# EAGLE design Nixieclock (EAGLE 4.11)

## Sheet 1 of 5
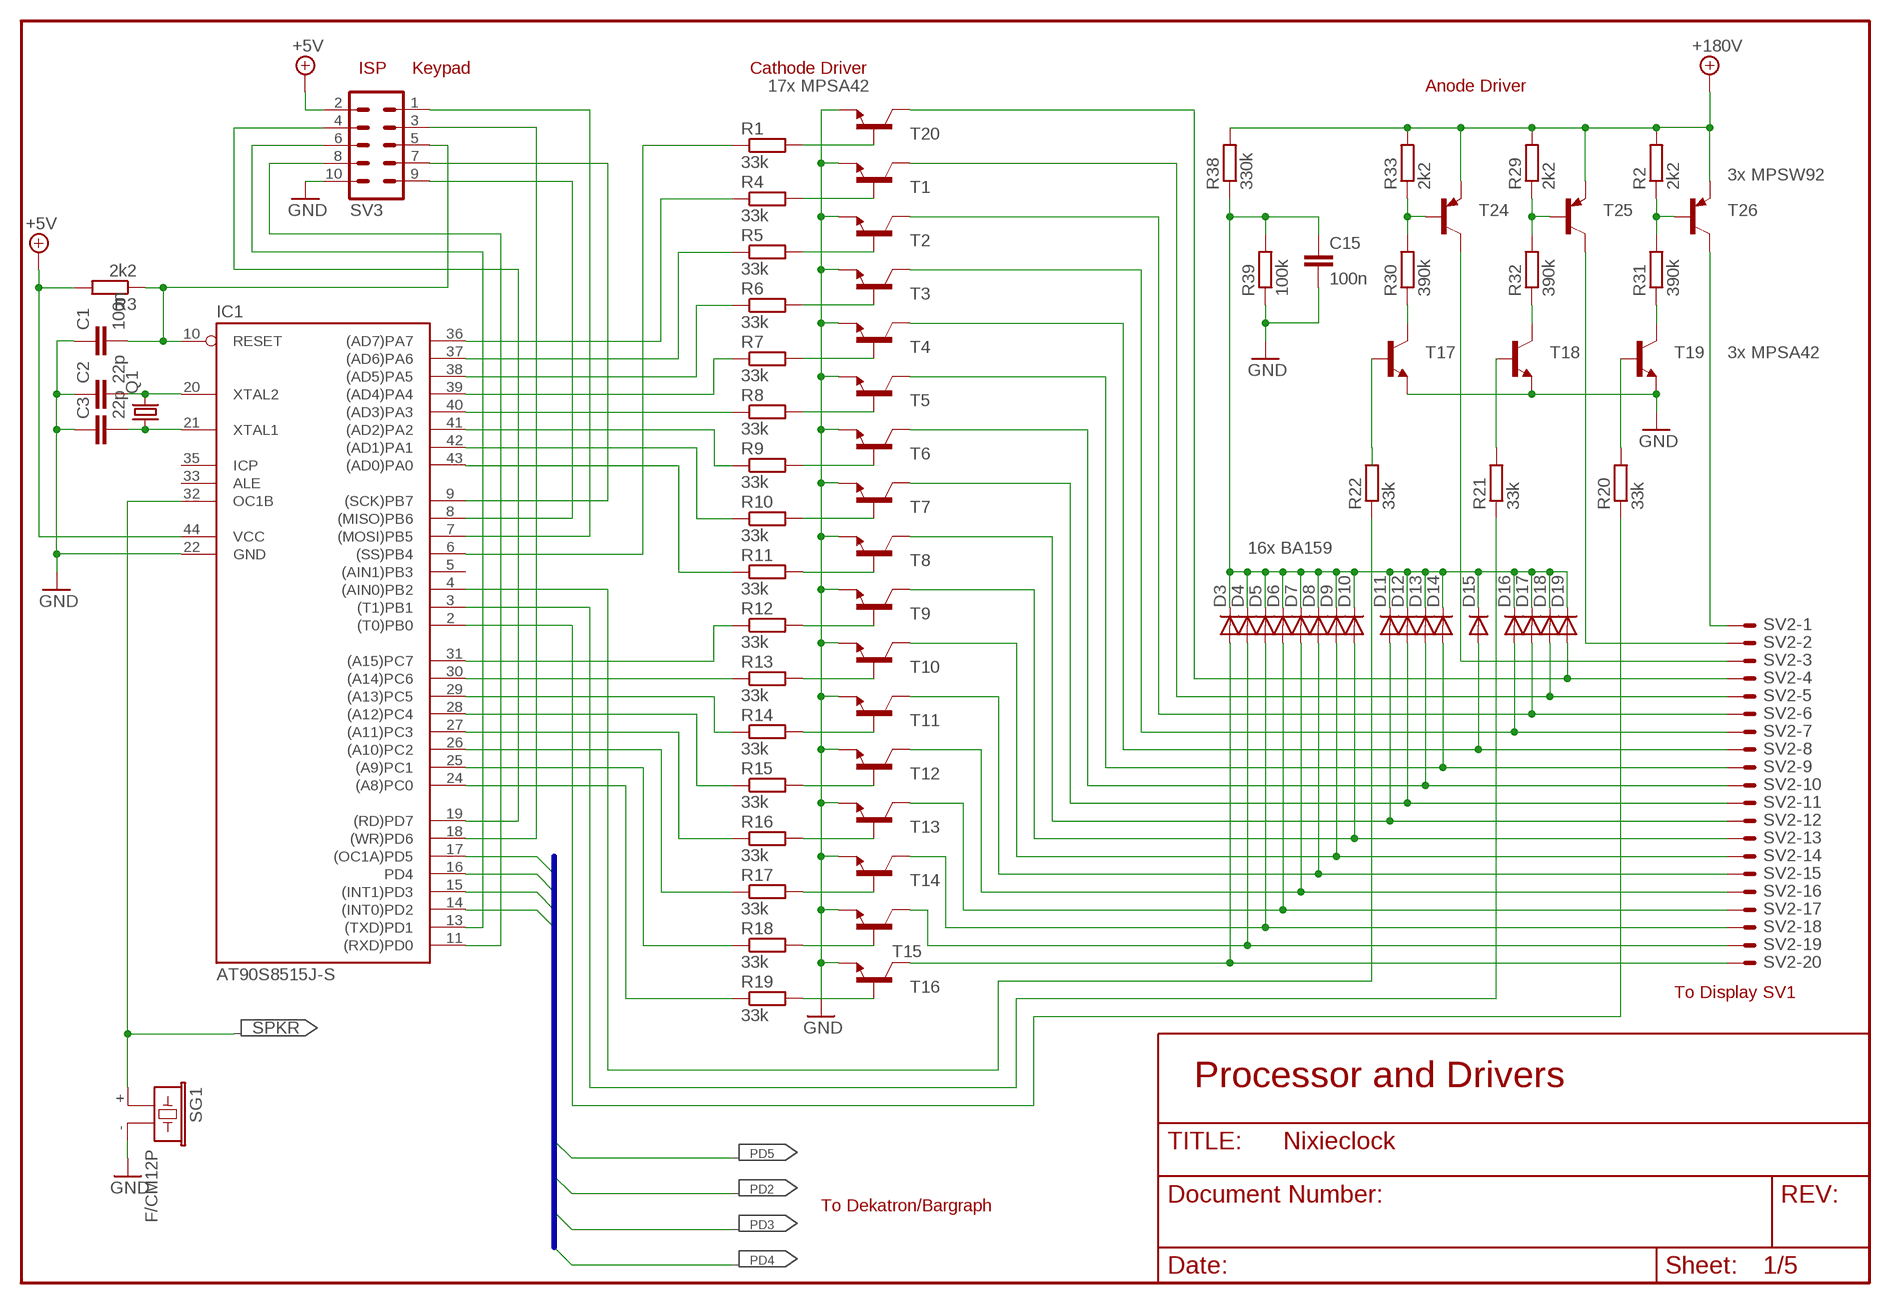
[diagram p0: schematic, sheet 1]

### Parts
C1  100n  C-EU025-024X044  [C025-024X044]
C2  22p  C-EU025-024X044  [C025-024X044]
C3  22p  C-EU025-024X044  [C025-024X044]
C15  100n  C-EU050-024X044  [C050-024X044]
D3  DIODE-D-7.5  [D-7.5]
D4  DIODE-D-7.5  [D-7.5]
D5  DIODE-D-7.5  [D-7.5]
D6  DIODE-D-7.5  [D-7.5]
D7  DIODE-D-7.5  [D-7.5]
D8  DIODE-D-7.5  [D-7.5]
D9  DIODE-D-7.5  [D-7.5]
D10  DIODE-D-7.5  [D-7.5]
D11  DIODE-D-7.5  [D-7.5]
D12  DIODE-D-7.5  [D-7.5]
D13  DIODE-D-7.5  [D-7.5]
D14  DIODE-D-7.5  [D-7.5]
D15  DIODE-D-7.5  [D-7.5]
D16  DIODE-D-7.5  [D-7.5]
D17  DIODE-D-7.5  [D-7.5]
D18  DIODE-D-7.5  [D-7.5]
D19  DIODE-D-7.5  [D-7.5]
IC1  AT90S8515J-S  [S44]
Q1  CRYTALHC49S  [HC49/S]
R1  33k  R-EU_0204/7  [0204/7]
R2  2k2  R-EU_0204/7  [0204/7]
R3  2k2  R-EU_0204/7  [0204/7]
R4  33k  R-EU_0204/7  [0204/7]
R5  33k  R-EU_0204/7  [0204/7]
R6  33k  R-EU_0204/7  [0204/7]
R7  33k  R-EU_0204/7  [0204/7]
R8  33k  R-EU_0204/7  [0204/7]
R9  33k  R-EU_0204/7  [0204/7]
R10  33k  R-EU_0204/7  [0204/7]
R11  33k  R-EU_0204/7  [0204/7]
R12  33k  R-EU_0204/7  [0204/7]
R13  33k  R-EU_0204/7  [0204/7]
R14  33k  R-EU_0204/7  [0204/7]
R15  33k  R-EU_0204/7  [0204/7]
R16  33k  R-EU_0204/7  [0204/7]
R17  33k  R-EU_0204/7  [0204/7]
R18  33k  R-EU_0204/7  [0204/7]
R19  33k  R-EU_0204/7  [0204/7]
R20  33k  R-EU_0204/7  [0204/7]
R21  33k  R-EU_0204/7  [0204/7]
R22  33k  R-EU_0204/7  [0204/7]
R29  2k2  R-EU_0204/7  [0204/7]
R30  390k  R-EU_0204/7  [0204/7]
R31  390k  R-EU_0204/7  [0204/7]
R32  390k  R-EU_0204/7  [0204/7]
R33  2k2  R-EU_0204/7  [0204/7]
R38  330k  R-EU_0207/7  [0207/7]
R39  100k  R-EU_0207/7  [0207/7]
SG1  F/CM12P  [F/CM12P]
SV2  ML20E  [ML20]
SV3  ML10  [ML10]
T1  MPSA42-NPN-TO92-CBE  [TO92-CBE]
T2  MPSA42-NPN-TO92-CBE  [TO92-CBE]
T3  MPSA42-NPN-TO92-CBE  [TO92-CBE]
T4  MPSA42-NPN-TO92-CBE  [TO92-CBE]
T5  MPSA42-NPN-TO92-CBE  [TO92-CBE]
T6  MPSA42-NPN-TO92-CBE  [TO92-CBE]
T7  MPSA42-NPN-TO92-CBE  [TO92-CBE]
T8  MPSA42-NPN-TO92-CBE  [TO92-CBE]
T9  MPSA42-NPN-TO92-CBE  [TO92-CBE]
T10  MPSA42-NPN-TO92-CBE  [TO92-CBE]
T11  MPSA42-NPN-TO92-CBE  [TO92-CBE]
T12  MPSA42-NPN-TO92-CBE  [TO92-CBE]
T13  MPSA42-NPN-TO92-CBE  [TO92-CBE]
T14  MPSA42-NPN-TO92-CBE  [TO92-CBE]
T15  MPSA42-NPN-TO92-CBE  [TO92-CBE]
T16  MPSA42-NPN-TO92-CBE  [TO92-CBE]
T17  MPSA42-NPN-TO92-CBE  [TO92-CBE]
T18  MPSA42-NPN-TO92-CBE  [TO92-CBE]
T19  MPSA42-NPN-TO92-CBE  [TO92-CBE]
T20  MPSA42-NPN-TO92-CBE  [TO92-CBE]
T24  MPSW92-PNP-TO92-CBE  [TO92-CBE]
T25  MPSW92-PNP-TO92-CBE  [TO92-CBE]
T26  MPSW92-PNP-TO92-CBE  [TO92-CBE]

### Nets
+5V: IC1.44(VCC) R3.2 SV3.2 ; also sheet 3,5
+180V: R2.2 R29.2 R33.2 R38.2 T24.E T25.E T26.E ; also sheet 3,4
GND: C1.1 C2.1 C3.1 C15.2 IC1.22(GND) R39.1 SG1.- SV3.10 T1.E T2.E T3.E T4.E T5.E T6.E T7.E T8.E T9.E T10.E T11.E T12.E T13.E T14.E T15.E T16.E T17.E T18.E T19.E T20.E ; also sheet 3,4,5
N$1: C2.2 IC1.20(XTAL2) Q1.2
N$2: C3.2 IC1.21(XTAL1) Q1.1
N$3: IC1.36((AD7)PA7) R4.1
N$4: C1.2 IC1.10(RESET) R3.1 SV3.5
N$5: IC1.37((AD6)PA6) R5.1
N$6: IC1.38((AD5)PA5) R6.1
N$7: IC1.39((AD4)PA4) R7.1
N$8: IC1.40((AD3)PA3) R8.1
N$9: IC1.41((AD2)PA2) R9.1
N$10: IC1.42((AD1)PA1) R10.1
N$11: IC1.43((AD0)PA0) R11.1
N$12: IC1.31((A15)PC7) R12.1
N$13: IC1.30((A14)PC6) R13.1
N$14: IC1.29((A13)PC5) R14.1
N$15: IC1.28((A12)PC4) R15.1
N$16: IC1.27((A11)PC3) R16.1
N$17: IC1.26((A10)PC2) R17.1
N$18: IC1.25((A9)PC1) R18.1
N$19: IC1.24((A8)PC0) R19.1
N$20: IC1.2((T0)PB0) R20.1
N$21: IC1.3((T1)PB1) R21.1
N$22: IC1.4((AIN0)PB2) R22.1
N$23: R30.2 R33.1 T24.B
N$24: R4.2 T1.B
N$25: R5.2 T2.B
N$32: R6.2 T3.B
N$33: R7.2 T4.B
N$34: R8.2 T5.B
N$35: R9.2 T6.B
N$36: R10.2 T7.B
N$37: R11.2 T8.B
N$38: R12.2 T9.B
N$39: R13.2 T10.B
N$40: R14.2 T11.B
N$41: R15.2 T12.B
N$42: R16.2 T13.B
N$43: R17.2 T14.B
N$44: R18.2 T15.B
N$45: R19.2 T16.B
N$46: D3.A SV2.20 T16.C
N$47: D4.A SV2.19 T15.C
N$48: D5.A SV2.18 T14.C
N$49: D6.A SV2.17 T13.C
N$50: D7.A SV2.16 T12.C
N$51: D8.A SV2.15 T11.C
N$52: D9.A SV2.14 T10.C
N$53: D10.A SV2.13 T9.C
N$54: D11.A SV2.12 T8.C
N$55: D12.A SV2.11 T7.C
N$56: D13.A SV2.10 T6.C
N$57: D14.A SV2.9 T5.C
N$58: D15.A SV2.8 T4.C
N$59: D16.A SV2.7 T3.C
N$60: D17.A SV2.6 T2.C
N$61: D18.A SV2.5 T1.C
N$62: D19.A SV2.4 T20.C
N$63: R1.2 T20.B
N$64: R29.1 R32.2 T25.B
N$65: R2.1 R31.2 T26.B
N$66: R31.1 T19.C
N$67: R32.1 T18.C
N$68: R30.1 T17.C
N$69: IC1.7((MOSI)PB5) SV3.1
N$70: IC1.6((SS)PB4) R1.1
N$71: R22.2 T17.B
N$72: R21.2 T18.B
N$73: R20.2 T19.B
N$75: SV2.2 T25.C
N$76: SV2.1 T26.C
N$77: IC1.9((SCK)PB7) SV3.7
N$78: IC1.8((MISO)PB6) SV3.9
N$81: C15.1 D3.C D4.C D5.C D6.C D7.C D8.C D9.C D10.C D11.C D12.C D13.C D14.C D15.C D16.C D17.C D18.C D19.C R38.1 R39.2
N$85: SV2.3 T24.C
N$103: IC1.19((RD)PD7) SV3.4
N$104: IC1.18((WR)PD6) SV3.3
N$105: IC1.13((TXD)PD1) SV3.6
N$106: IC1.11((RXD)PD0) SV3.8
PD2: IC1.14((INT0)PD2) ; also sheet 4
PD3: IC1.15((INT1)PD3) ; also sheet 4
PD4: IC1.16(PD4) ; also sheet 4
PD5: IC1.17((OC1A)PD5) ; also sheet 4
SPKR: IC1.32(OC1B) SG1.+ ; also sheet 3
Unconnected: IC1.1(NC4) IC1.5((AIN1)PB3) IC1.12(NC3) IC1.23(NC2) IC1.33(ALE) IC1.34(NC1) IC1.35(ICP)

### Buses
PD[0..7]

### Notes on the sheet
- ISP | Keypad | Cathode Driver
- 17x MPSA42 | Anode Driver
- 3x MPSW92
- 3x MPSA42
- 16x BA159
- To Display SV1
- Processor and Drivers
- To Dekatron/Bargraph

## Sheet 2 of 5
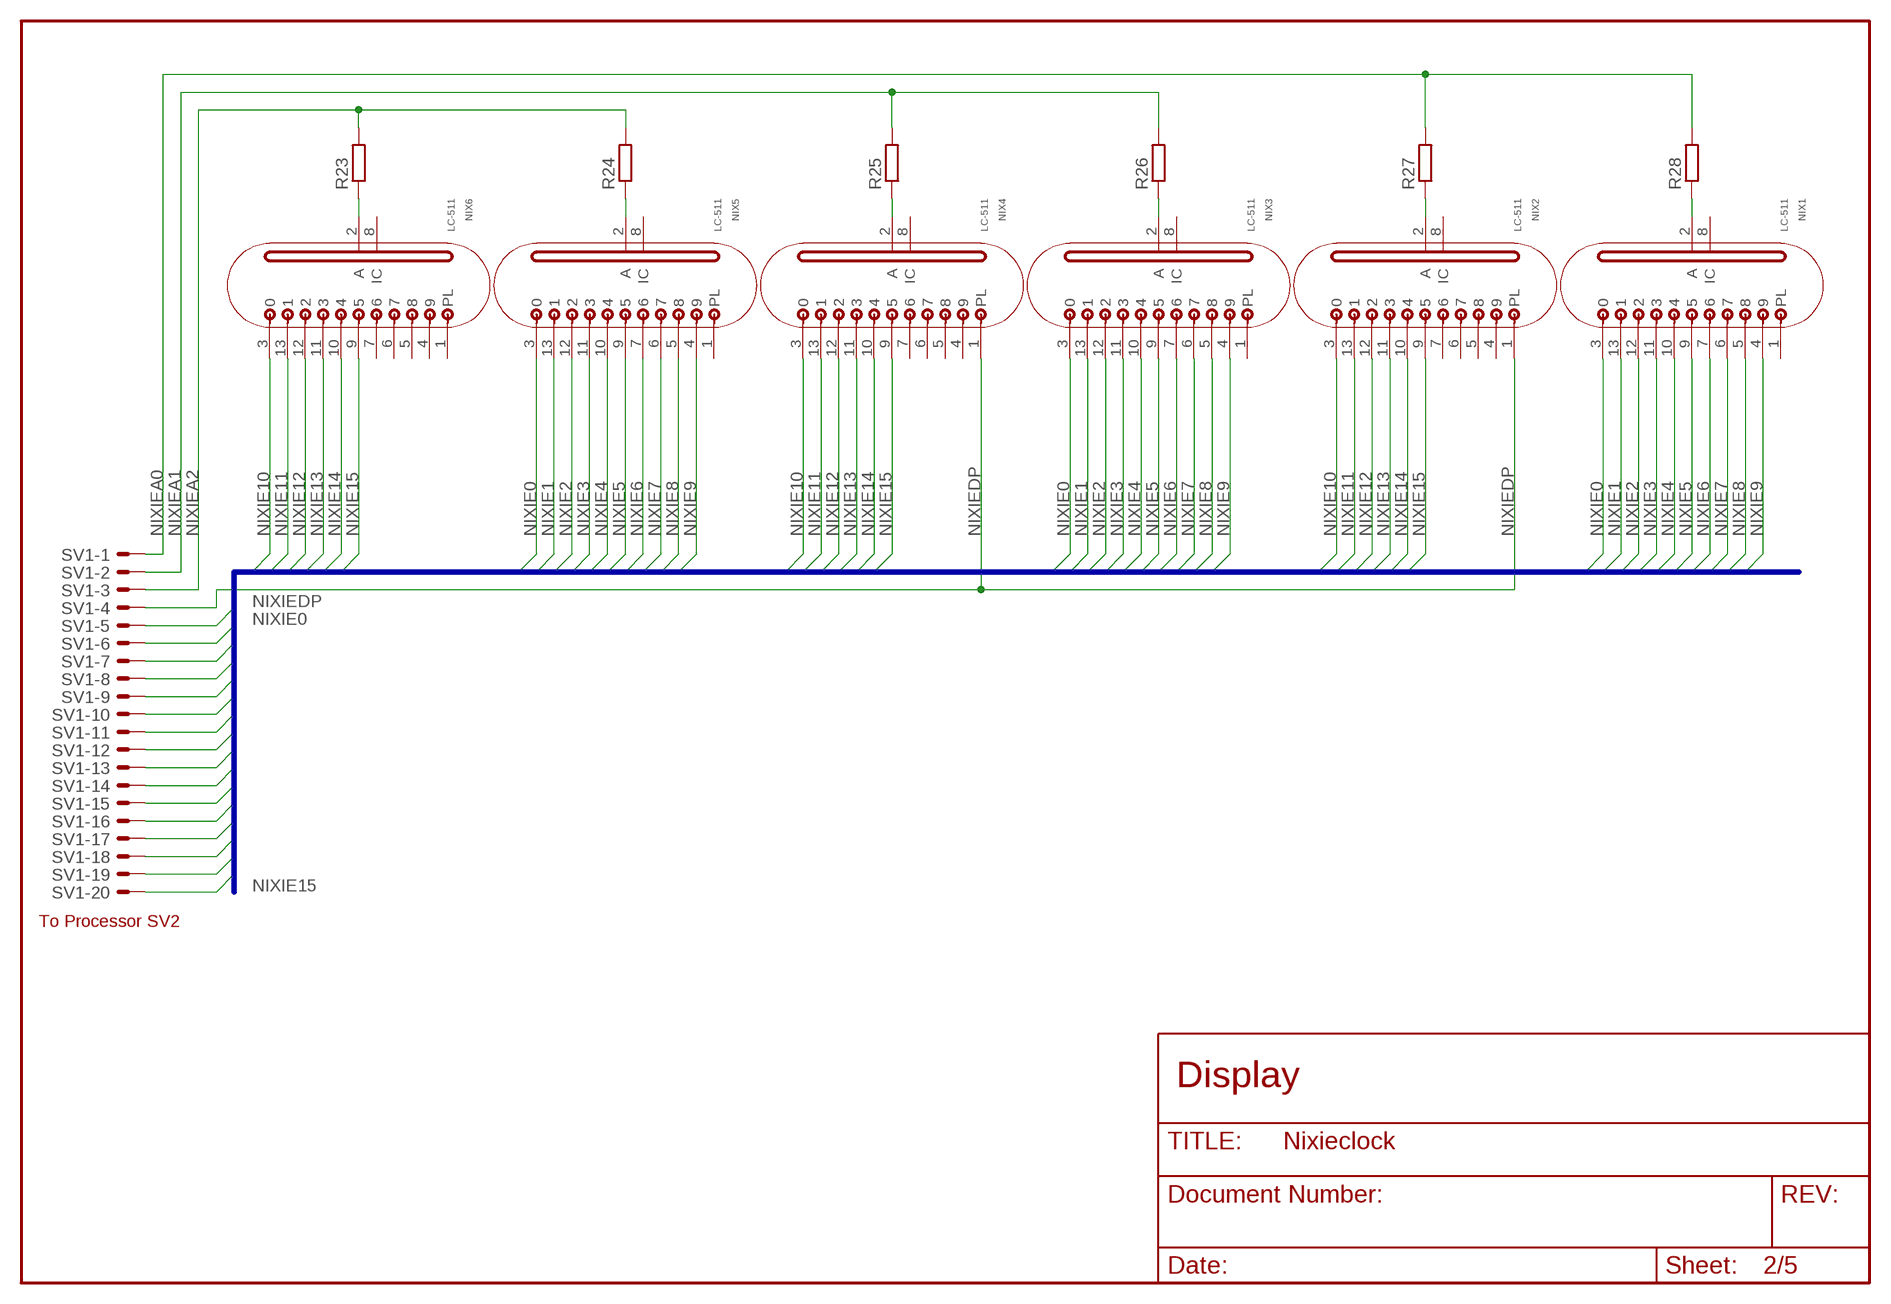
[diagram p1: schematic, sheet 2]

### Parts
NIX1  LC-511  [NIXIE-13]
NIX2  LC-511  [NIXIE-13]
NIX3  LC-511  [NIXIE-13]
NIX4  LC-511  [NIXIE-13]
NIX5  LC-511  [NIXIE-13]
NIX6  LC-511  [NIXIE-13]
R23  R-EU_0207/10  [0207/10]
R24  R-EU_0207/10  [0207/10]
R25  R-EU_0207/10  [0207/10]
R26  R-EU_0207/10  [0207/10]
R27  R-EU_0207/10  [0207/10]
R28  R-EU_0207/10  [0207/10]
SV1  ML20E  [ML20]

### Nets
N$26: NIX6.2(A) R23.1
N$27: NIX5.2(A) R24.1
N$28: NIX4.2(A) R25.1
N$29: NIX3.2(A) R26.1
N$30: NIX2.2(A) R27.1
N$31: NIX1.2(A) R28.1
NIXIE0: NIX1.3 NIX3.3 NIX5.3 SV1.5
NIXIE1: NIX1.13 NIX3.13 NIX5.13 SV1.6
NIXIE2: NIX1.12 NIX3.12 NIX5.12 SV1.7
NIXIE3: NIX1.11 NIX3.11 NIX5.11 SV1.8
NIXIE4: NIX1.10 NIX3.10 NIX5.10 SV1.9
NIXIE5: NIX1.9 NIX3.9 NIX5.9 SV1.10
NIXIE6: NIX1.7 NIX3.7 NIX5.7 SV1.11
NIXIE7: NIX1.6 NIX3.6 NIX5.6 SV1.12
NIXIE8: NIX1.5 NIX3.5 NIX5.5 SV1.13
NIXIE9: NIX1.4 NIX3.4 NIX5.4 SV1.14
NIXIE10: NIX2.3 NIX4.3 NIX6.3 SV1.15
NIXIE11: NIX2.13 NIX4.13 NIX6.13 SV1.16
NIXIE12: NIX2.12 NIX4.12 NIX6.12 SV1.17
NIXIE13: NIX2.11 NIX4.11 NIX6.11 SV1.18
NIXIE14: NIX2.10 NIX4.10 NIX6.10 SV1.19
NIXIE15: NIX2.9 NIX4.9 NIX6.9 SV1.20
NIXIEA0: R27.2 R28.2 SV1.1
NIXIEA1: R25.2 R26.2 SV1.2
NIXIEA2: R23.2 R24.2 SV1.3
NIXIEDP: NIX2.1(PL) NIX4.1(PL) SV1.4
Unconnected: NIX1.1(PL) NIX1.8(IC) NIX2.4 NIX2.5 NIX2.6 NIX2.7 NIX2.8(IC) NIX3.1(PL) NIX3.8(IC) NIX4.4 NIX4.5 NIX4.6 NIX4.7 NIX4.8(IC) NIX5.1(PL) NIX5.8(IC) NIX6.1(PL) NIX6.4 NIX6.5 NIX6.6 NIX6.7 NIX6.8(IC)

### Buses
NIXIE[0..15]

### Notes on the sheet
- To Processor SV2
- Display

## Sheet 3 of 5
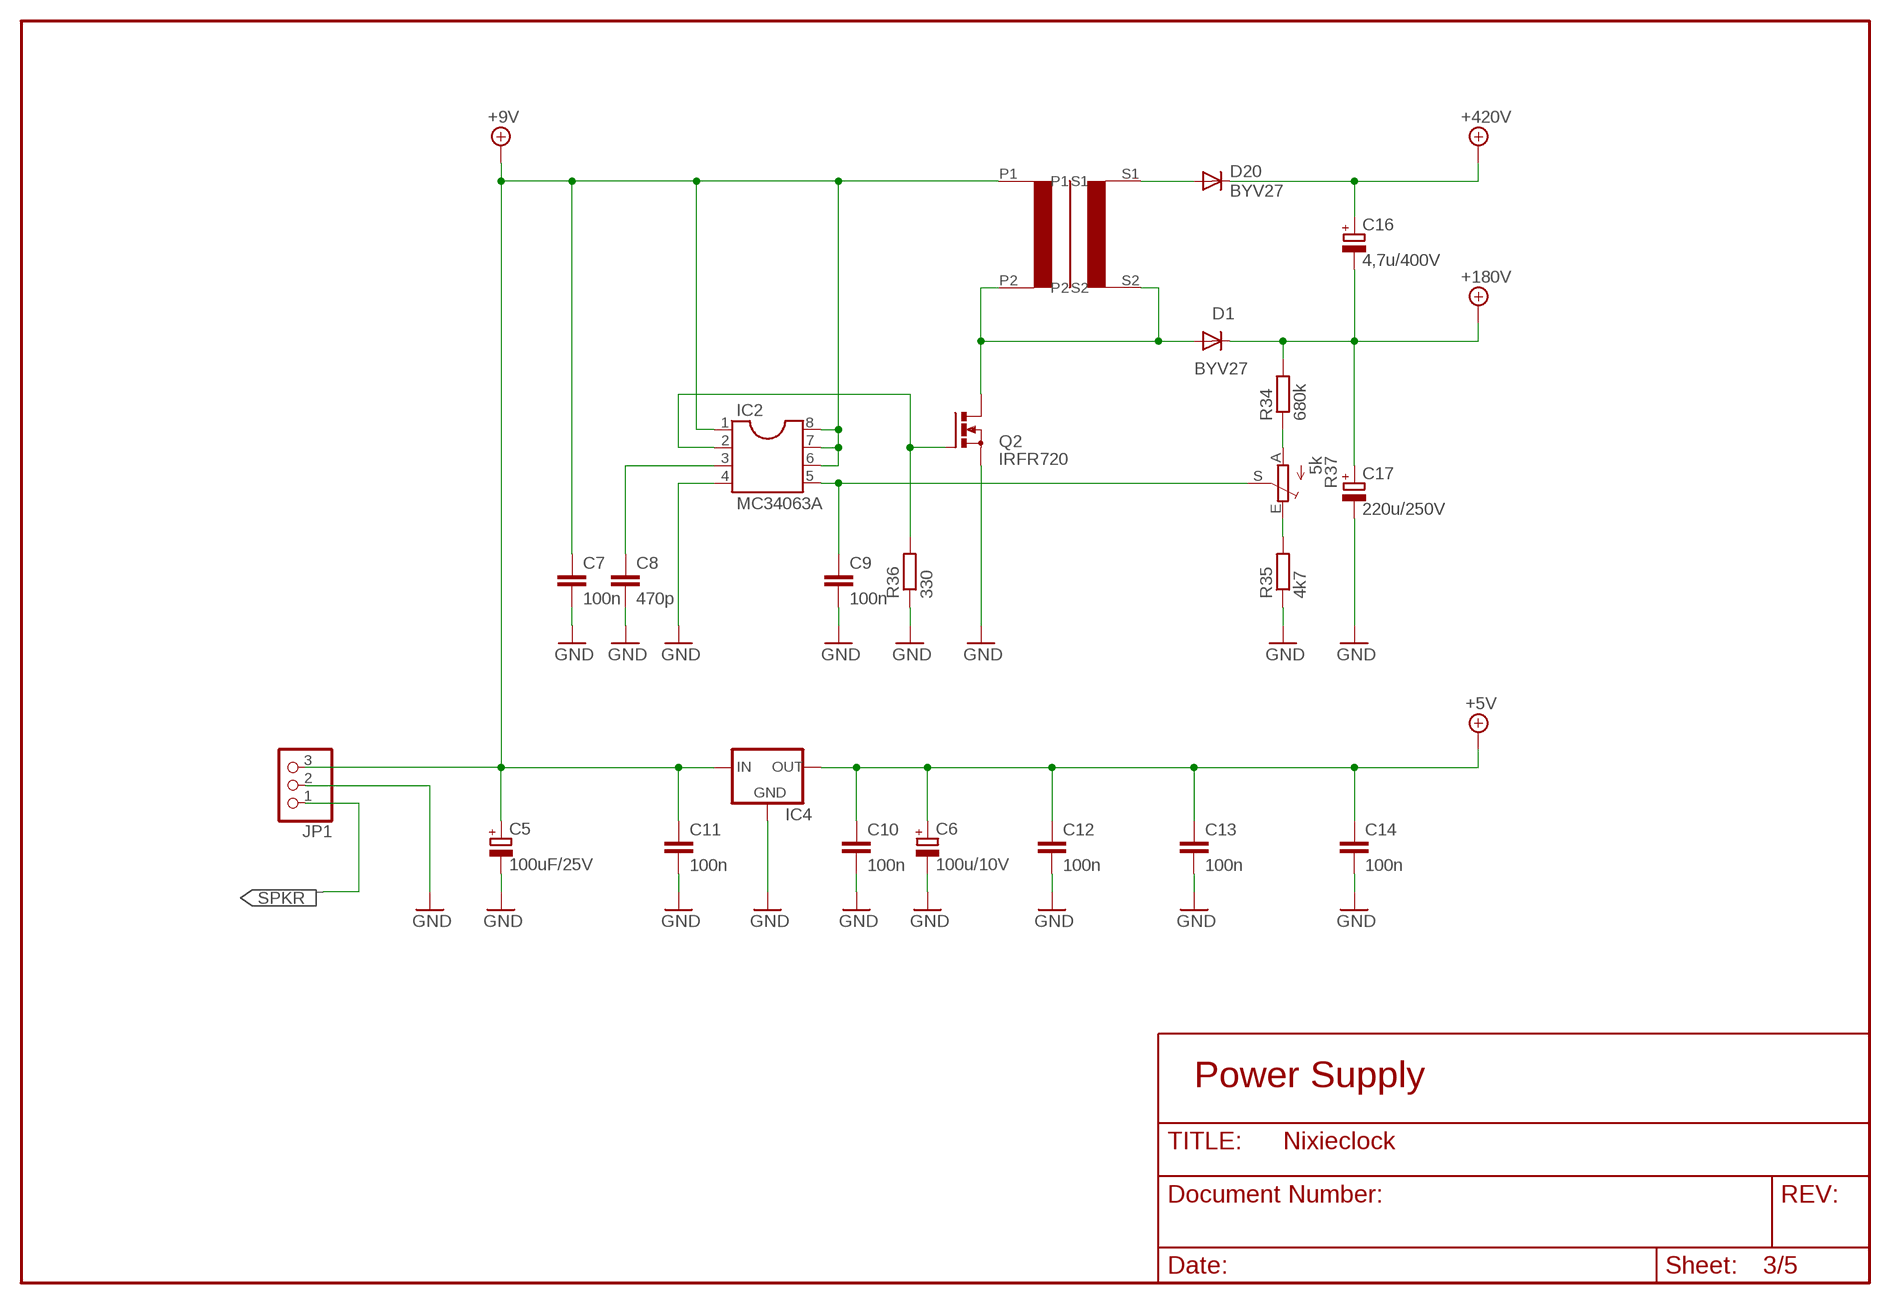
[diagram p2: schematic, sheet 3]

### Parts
C5  100uF/25V  CPOL-EUE5-6  [E5-6]
C6  100u/10V  CPOL-EUE5-6  [E5-6]
C7  100n  C-EU025-024X044  [C025-024X044]
C8  470p  C-EU025-024X044  [C025-024X044]
C9  100n  C-EU025-024X044  [C025-024X044]
C10  100n  C-EU025-024X044  [C025-024X044]
C11  100n  C-EU025-024X044  [C025-024X044]
C12  100n  C-EU025-024X044  [C025-024X044]
C13  100n  C-EU025-024X044  [C025-024X044]
C14  100n  C-EU025-024X044  [C025-024X044]
C16  4,7u/400V  CPOL-EUE3.5-10  [E3,5-10]
C17  220u/250V  CPOL-EUE3.5-10  [E3,5-10]
D1  BYV27  [SOD57-10]
D20  BYV27  [SOD57-10]
IC2  MC34063A  DIL8  [DIL08]
IC4  78XXL  [78XXL]
JP1  PINHD-1X3  [1X03]
Q2  IRFR720  PMOSFET_N  [TO220AHS]
R34  680k  R-EU_0204/7  [0204/7]
R35  4k7  R-EU_0204/7  [0204/7]
R36  330  R-EU_0204/7  [0204/7]
R37  5k  TRIM_EU-LI10  [LI10]
U$1  TRANSFORMER  [TOROID]

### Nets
+5V: C6.+ C10.1 C12.1 C13.1 C14.1 IC4.OUT ; also sheet 1,5
+9V: C5.+ C7.1 C11.1 IC2.1 IC2.6 IC2.7 IC2.8 IC4.IN JP1.3 U$1.P1 ; also sheet 5
+180V: C16.- C17.+ D1.C R34.2 ; also sheet 1,4
+420V: C16.+ D20.C ; also sheet 4
GND: C5.- C6.- C7.2 C8.2 C9.2 C10.2 C11.2 C12.2 C13.2 C14.2 C17.- IC2.4 IC4.GND JP1.2 Q2.E(S) R35.1 R36.1 ; also sheet 1,4,5
N$82: C8.1 IC2.3
N$83: IC2.2 Q2.B(G) R36.2
N$84: D1.A Q2.C(D) U$1.P2 U$1.S2
N$86: C9.1 IC2.5 R37.S
N$87: R34.1 R37.A
N$88: R35.2 R37.E
N$90: D20.A U$1.S1
SPKR: JP1.1 ; also sheet 1

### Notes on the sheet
- Power Supply

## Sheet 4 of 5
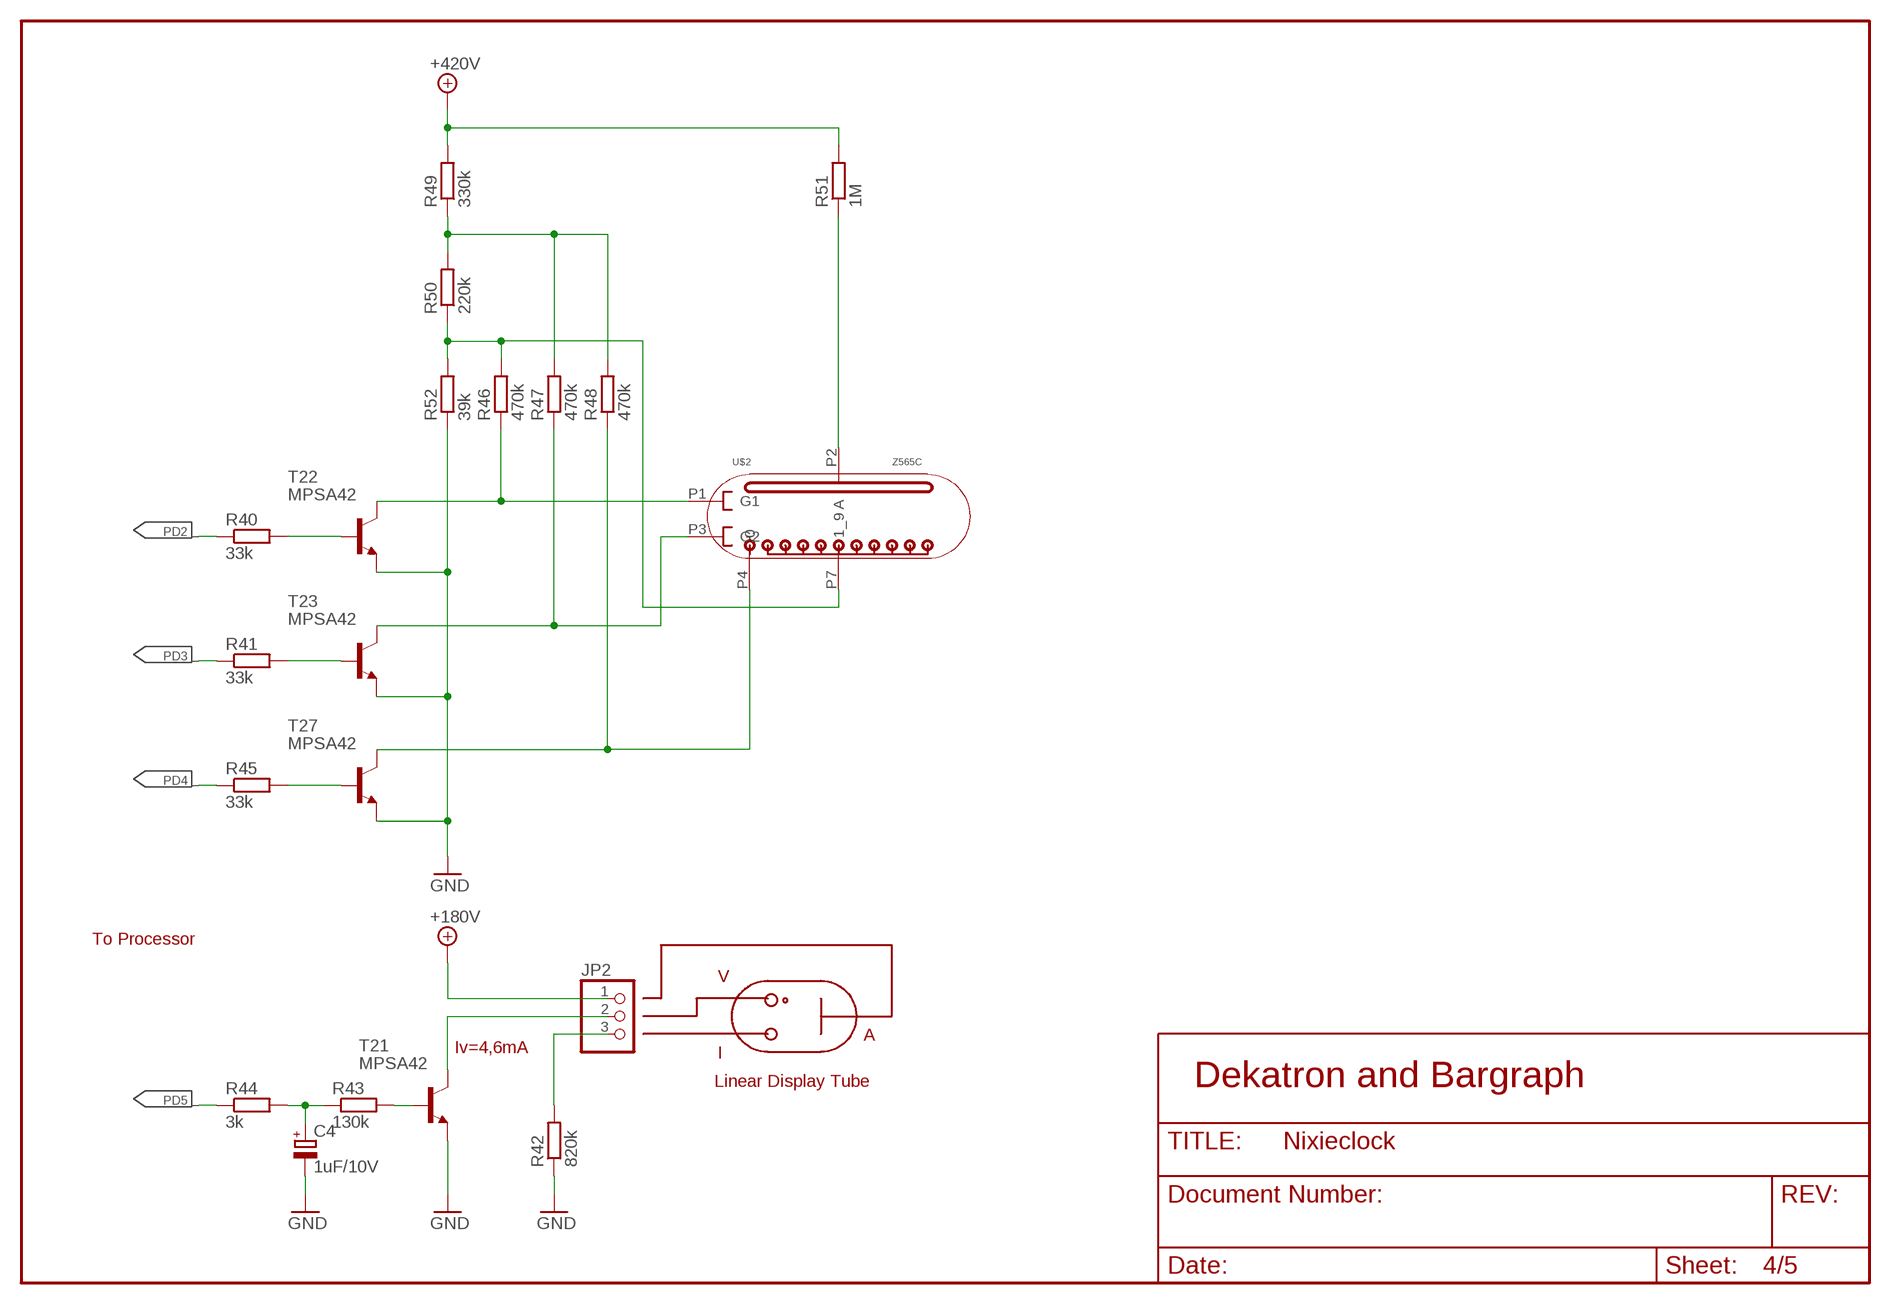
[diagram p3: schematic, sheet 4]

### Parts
C4  1uF/10V  CPOL-EUE2.5-5  [E2,5-5]
JP2  PINHD-1X3  [1X03]
R40  33k  R-EU_0207/7  [0207/7]
R41  33k  R-EU_0207/7  [0207/7]
R42  820k  R-EU_0207/7  [0207/7]
R43  130k  R-EU_0207/7  [0207/7]
R44  3k  R-EU_0207/7  [0207/7]
R45  33k  R-EU_0207/7  [0207/7]
R46  470k  R-EU_0207/7  [0207/7]
R47  470k  R-EU_0207/7  [0207/7]
R48  470k  R-EU_0207/7  [0207/7]
R49  330k  R-EU_0207/7  [0207/7]
R50  220k  R-EU_0207/7  [0207/7]
R51  1M  R-EU_0207/7  [0207/7]
R52  39k  R-EU_0207/7  [0207/7]
T21  MPSA42  MPSA42-NPN-TO92-CBE  [TO92-CBE]
T22  MPSA42  MPSA42-NPN-TO92-CBE  [TO92-CBE]
T23  MPSA42  MPSA42-NPN-TO92-CBE  [TO92-CBE]
T27  MPSA42  MPSA42-NPN-TO92-CBE  [TO92-CBE]
U$2  Z565C  [DEKATRON]

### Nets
+180V: JP2.1 ; also sheet 1,3
+420V: R49.2 R51.2 ; also sheet 3
G0_: R40.2 T22.B
GND: C4.- R42.1 R52.1 T21.E T22.E T23.E T27.E ; also sheet 1,3,5
N$91: JP2.3 R42.2
N$92: JP2.2 T21.C
N$93: R47.2 R48.2 R49.1 R50.2
N$94: R43.2 T21.B
N$95: C4.+ R43.1 R44.2
N$96: R46.2 R50.1 R52.2 U$2.P7(1_9)
N$97: R46.1 T22.C U$2.P1(G1)
N$98: R47.1 T23.C U$2.P3(G2)
N$99: R48.1 T27.C U$2.P4
N$100: R51.1 U$2.P2(A)
N$101: R41.2 T23.B
N$102: R45.2 T27.B
PD2: R40.1 ; also sheet 1
PD3: R41.1 ; also sheet 1
PD4: R45.1 ; also sheet 1
PD5: R44.1 ; also sheet 1

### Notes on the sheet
- To Processor
- V
- A
- Iv=4,6mA
- I
- Linear Display Tube | Dekatron and Bargraph

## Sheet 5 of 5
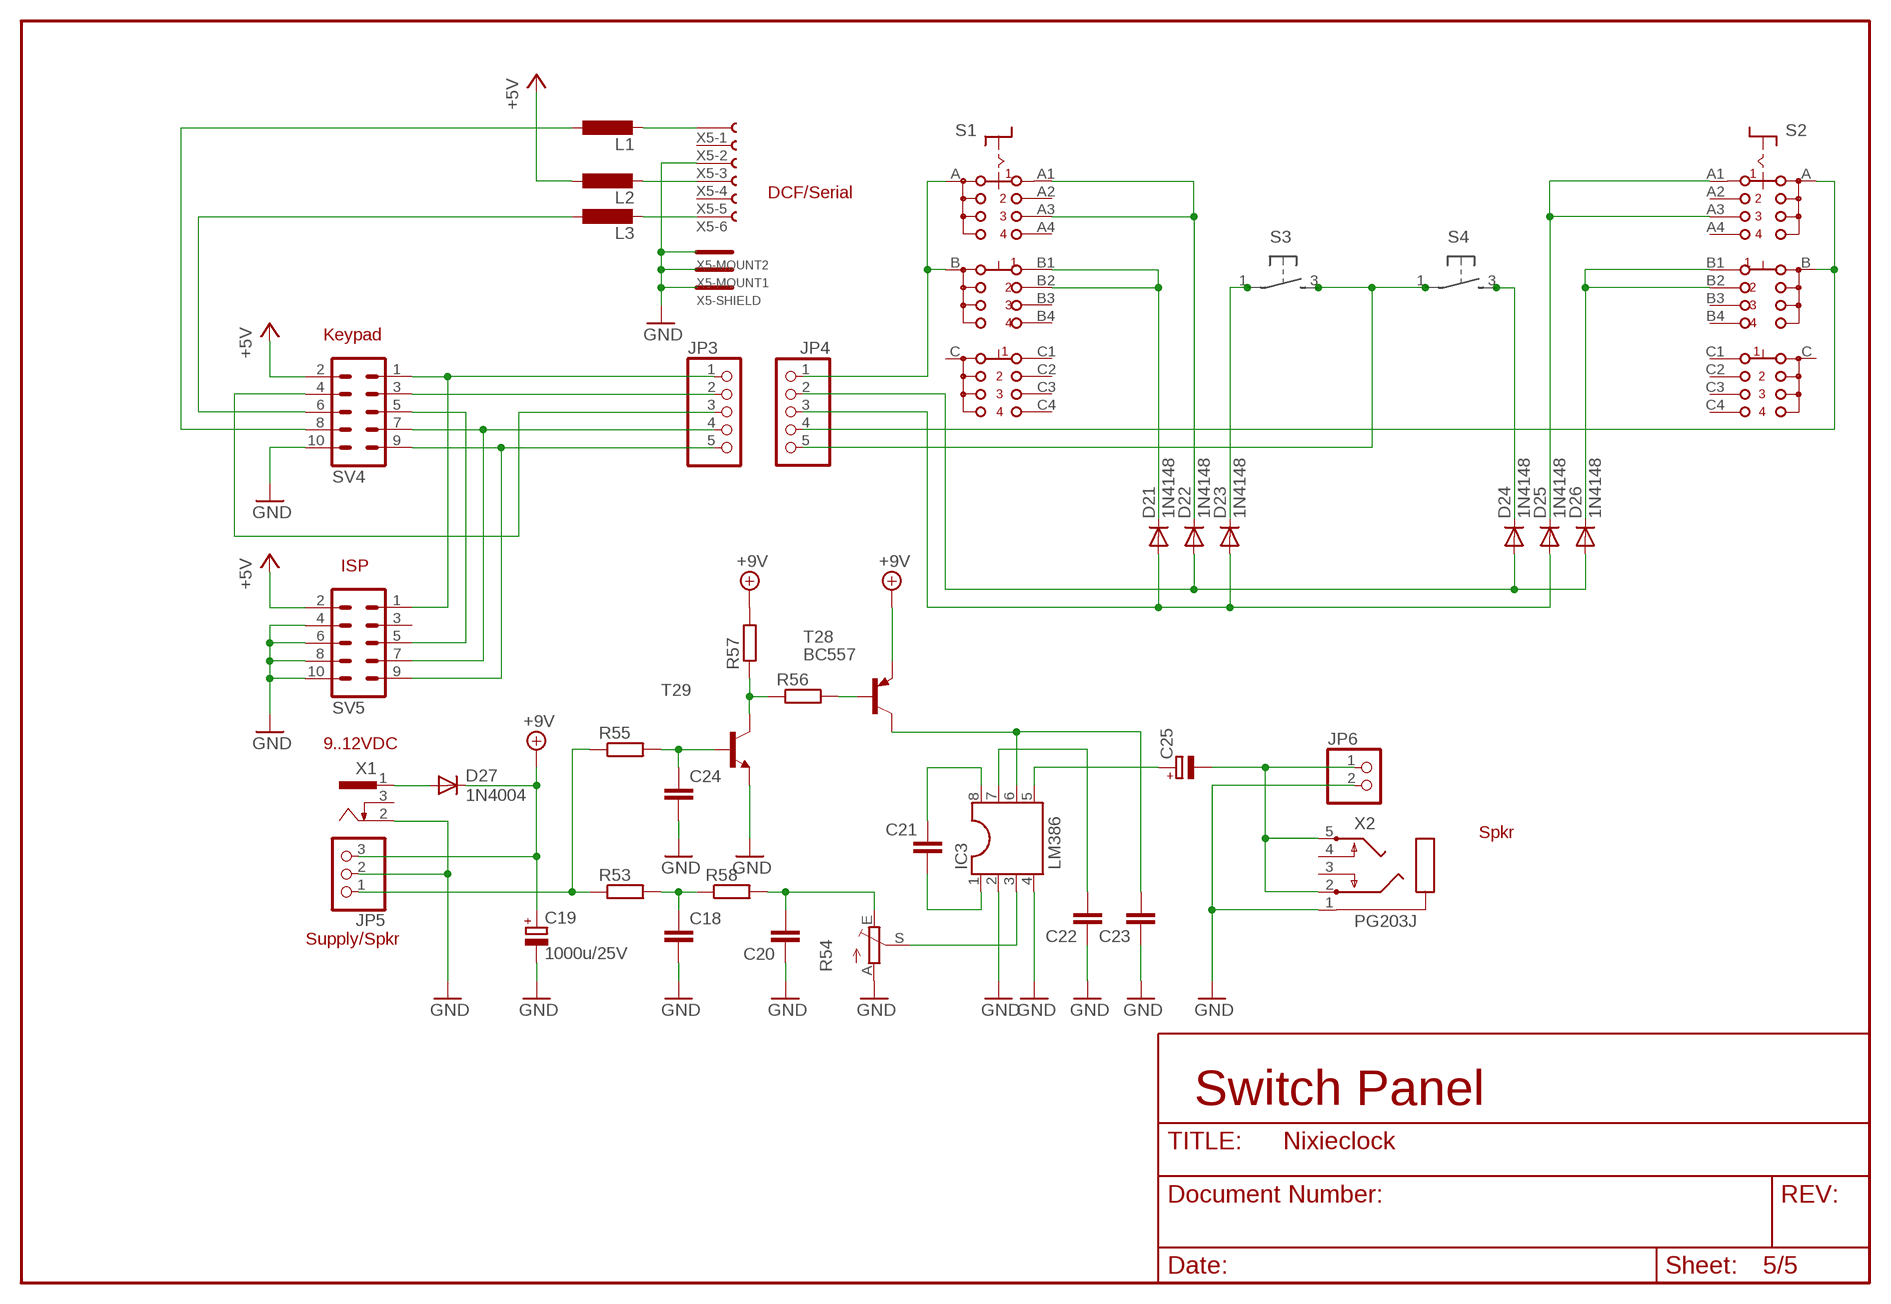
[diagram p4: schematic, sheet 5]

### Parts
C18  C-EU025-025X050  [C025-025X050]
C19  1000u/25V  CPOL-EUE7.5-16  [E7,5-16]
C20  C-EU025-025X050  [C025-025X050]
C21  C-EU025-025X050  [C025-025X050]
C22  C-EU025-025X050  [C025-025X050]
C23  C-EU025-025X050  [C025-025X050]
C24  C-EU025-025X050  [C025-025X050]
C25  CPOL-EUE2.5-6  [E2,5-6]
D21  1N4148  [DO35-10]
D22  1N4148  [DO35-10]
D23  1N4148  [DO35-10]
D24  1N4148  [DO35-10]
D25  1N4148  [DO35-10]
D26  1N4148  [DO35-10]
D27  1N4004  [DO41-10]
IC3  LM386  DIL8  [DIL08]
JP3  PINHD-1X5  [1X05]
JP4  PINHD-1X5  [1X05]
JP5  PINHD-1X3  [1X03]
JP6  PINHD-1X2  [1X02]
L1  L-EU0207/10  [0207/10]
L2  L-EU0207/10  [0207/10]
L3  L-EU0207/10  [0207/10]
R53  R-EU_0207/7  [0207/7]
R54  TRIM_EU-LI10  [LI10]
R55  R-EU_0207/7  [0207/7]
R56  R-EU_0204/7  [0204/7]
R57  R-EU_0204/7  [0204/7]
R58  R-EU_0207/7  [0207/7]
S1  CK103X04  [CK103X04]
S2  CK103X04  [CK103X04]
S3  MEC1ZC  [MEC1ZC]
S4  MEC1ZC  [MEC1ZC]
SV4  ML10  [ML10]
SV5  ML10L  [ML10L]
T28  BC557  BC557C-PNP-TO92-EBC  [TO92-EBC]
T29  BC547B-NPN-TO92-EBC  [TO92-EBC]
X1  733989-55  [733989-5]
X2  PG203J  [PG203J]
X5  MiniDIN-6  MINI-6  [MINI-6]

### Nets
+5V: L2.1 SV4.2 SV5.2 ; also sheet 1,3
+9V: C19.+ D27.C JP5.3 R57.2 T28.E ; also sheet 3
C1: D22.A D24.A D26.A JP3.2 JP4.2 SV4.3
C2: D21.A D23.A D25.A JP3.3 JP4.3 SV4.4
GND: C18.2 C19.- C20.1 C22.1 C23.1 C24.2 IC3.2 IC3.4 JP5.2 JP6.2 R54.A SV4.10 SV5.4 SV5.6 SV5.8 SV5.10 T29.E X1.2 X2.1 X5.D X5.M X5.M1 X5.M2 ; also sheet 1,3,4
N$74: JP5.1 R53.1 R55.1
N$79: C18.1 R53.2 R58.1
N$80: D27.A X1.1
N$89: D21.C S1.B1 S1.B2
N$107: D22.C S1.A1 S1.A3
N$108: C20.2 R54.E R58.2
N$109: C21.2 IC3.1
N$110: D25.C S2.A1 S2.A3
N$111: C21.1 IC3.8
N$112: IC3.3 R54.S
N$113: C25.+ IC3.5
N$114: D26.C S2.B1 S2.B2
N$115: D24.C S4.3 S4.4
N$116: D23.C S3.1 S3.2
N$117: C25.- JP6.1 X2.2 X2.5
N$118: C22.2 IC3.7
N$119: SV4.5 SV5.5
N$120: C23.2 IC3.6 T28.C
N$121: C24.1 R55.2 T29.B
N$122: L3.1 SV4.6
N$123: L1.1 SV4.8
N$124: R56.2 T28.B
N$125: R56.1 R57.1 T29.C
N$126: L1.2 X5.C
N$127: L3.2 X5.E
N$128: L2.2 X5.A
R1: JP3.1 JP4.1 S1.A S1.B SV4.1 SV5.1
R2: JP3.4 JP4.4 S2.A S2.B SV4.7 SV5.7
R3: JP3.5 JP4.5 S3.3 S3.4 S4.1 S4.2 SV4.9 SV5.9
Unconnected: S1.A2 S1.A4 S1.B3 S1.B4 S1.C S1.C1 S1.C2 S1.C3 S1.C4 S2.A2 S2.A4 S2.B3 S2.B4 S2.C S2.C1 S2.C2 S2.C3 S2.C4 SV5.3 X1.3 X2.3 X2.4 X5.B X5.H

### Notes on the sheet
- DCF/Serial
- Keypad
- ISP
- 9..12VDC
- Spkr
- Supply/Spkr
- Switch Panel

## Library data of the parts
C1-C3 C7-C15 C18 C20-C24 = rcl:C-EU: CAPACITOR, European symbol
C4-C6 C16 C17 C19 C25 = rcl:CPOL-EU: POLARIZED CAPACITOR, European symbol
D1 D20 = diode:BYV27: DIODE
D3-D19 = diode:DIODE-: DIODE
D21-D26 = diode:1N4148: DIODE
D27 = diode:1N4004: DIODE
IC1 = atmel:AT90S8515: MICROCONTROLLER 8 Kbytes FLASH 512 bytes SRAM 512 bytes EEPROM UART
IC2 IC3 = ic-package:DIL8: Dual In Line
IC4 = v-reg:78XXL: VOLTAGE REGULATOR
JP1 JP2 JP5 = pinhead:PINHD-1X3: PIN HEADER
JP3 JP4 = pinhead:PINHD-1X5: PIN HEADER
JP6 = pinhead:PINHD-1X2: PIN HEADER
L1-L3 = rcl:L-EU: INDUCTOR, European symbol
NIX1-NIX6 = Nixie:LC-511
Q1 = crystal:CRYTAL: CRYSTAL
Q2 = transistor-power:PMOSFET_N: Power MOSFET N-Channel
R1-R36 R38-R53 R55-R58 = rcl:R-EU_: RESISTOR, European symbol
R37 R54 = pot:TRIM_EU-: POTENTIOMETER
S1 S2 = switch:CK103X04: ROTARY SWITCH C&K
S3 S4 = switch-mec:MEC1ZC
SG1 = buzzer:F/CM12P: BUZZER
SV1 SV2 = con-ml:ML20E: HARTING
SV3 SV4 = con-ml:ML10: HARTING
SV5 = con-ml:ML10L: HARTING
T1-T23 T27 T29 = transistor:*-NPN-: NPN Transistror
T24-T26 T28 = transistor:*-PNP-: PNP Transistror
U$1 = Nixie:TRANSFORMER
U$2 = Nixie:Z565C
X1 = con-conrad:733989-55: FEMALE PRINT CONNECTOR 1.1 mm, FUK HING Industries, distributor Conrad
X2 = con-hirschmann:PG203J: MIC/HEADPHONE JACK KS-S stereo microphone/headphone jack PG203JN (Schukat)
X5 = HIRSCHM:MINI-6

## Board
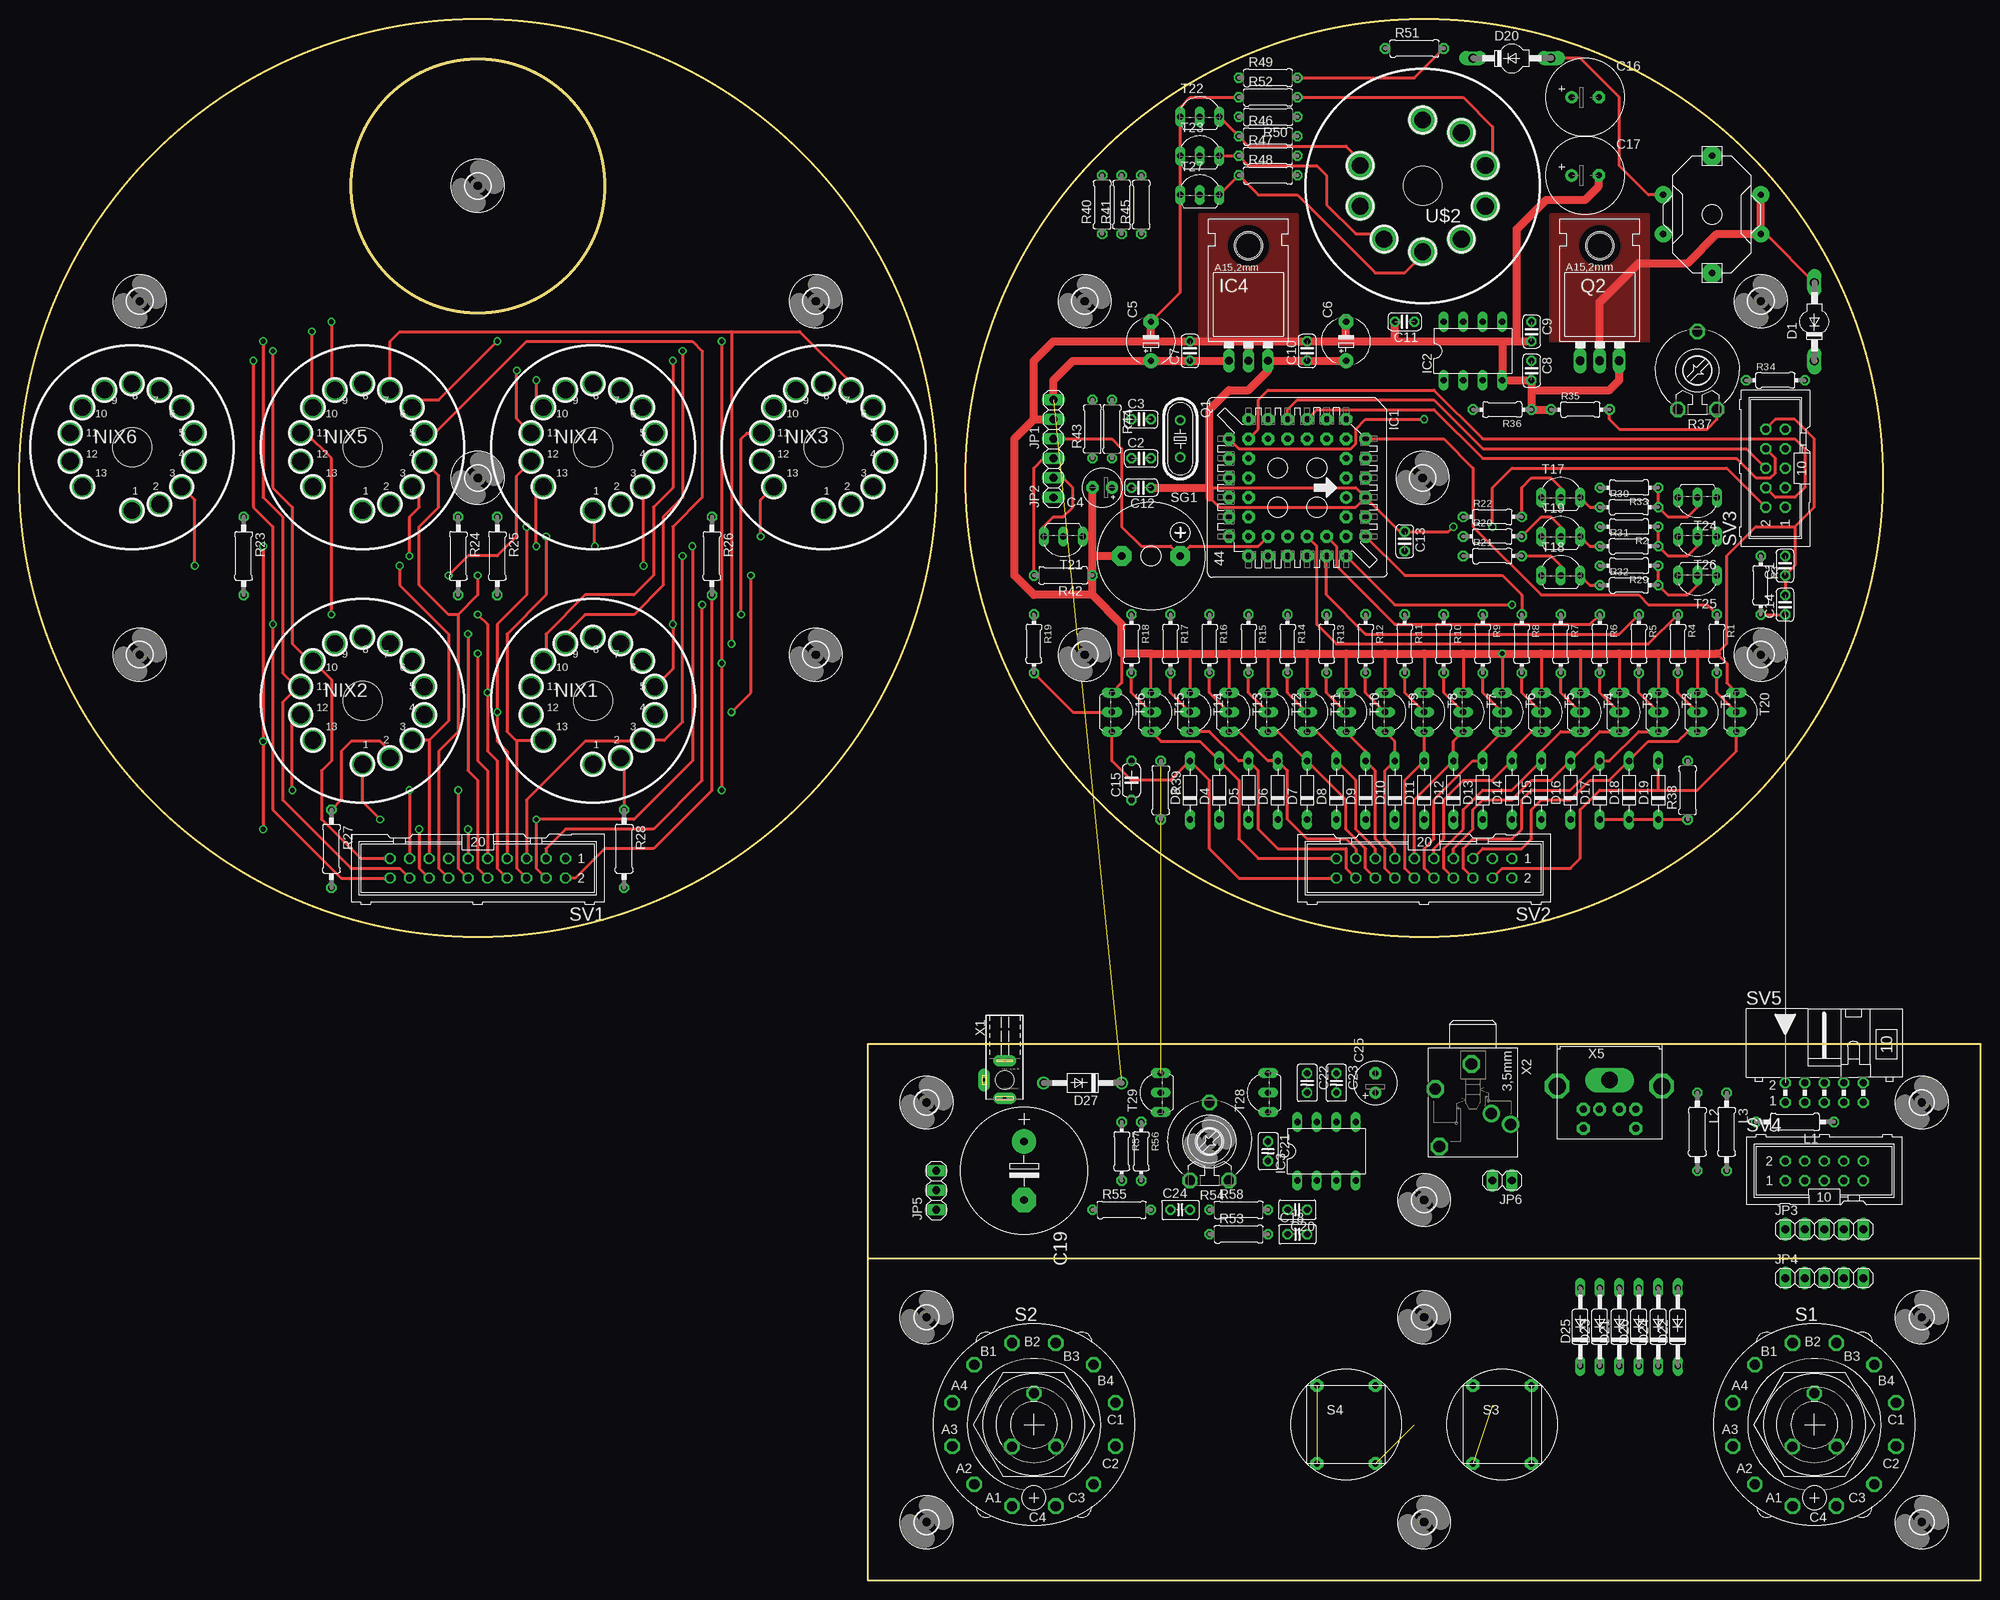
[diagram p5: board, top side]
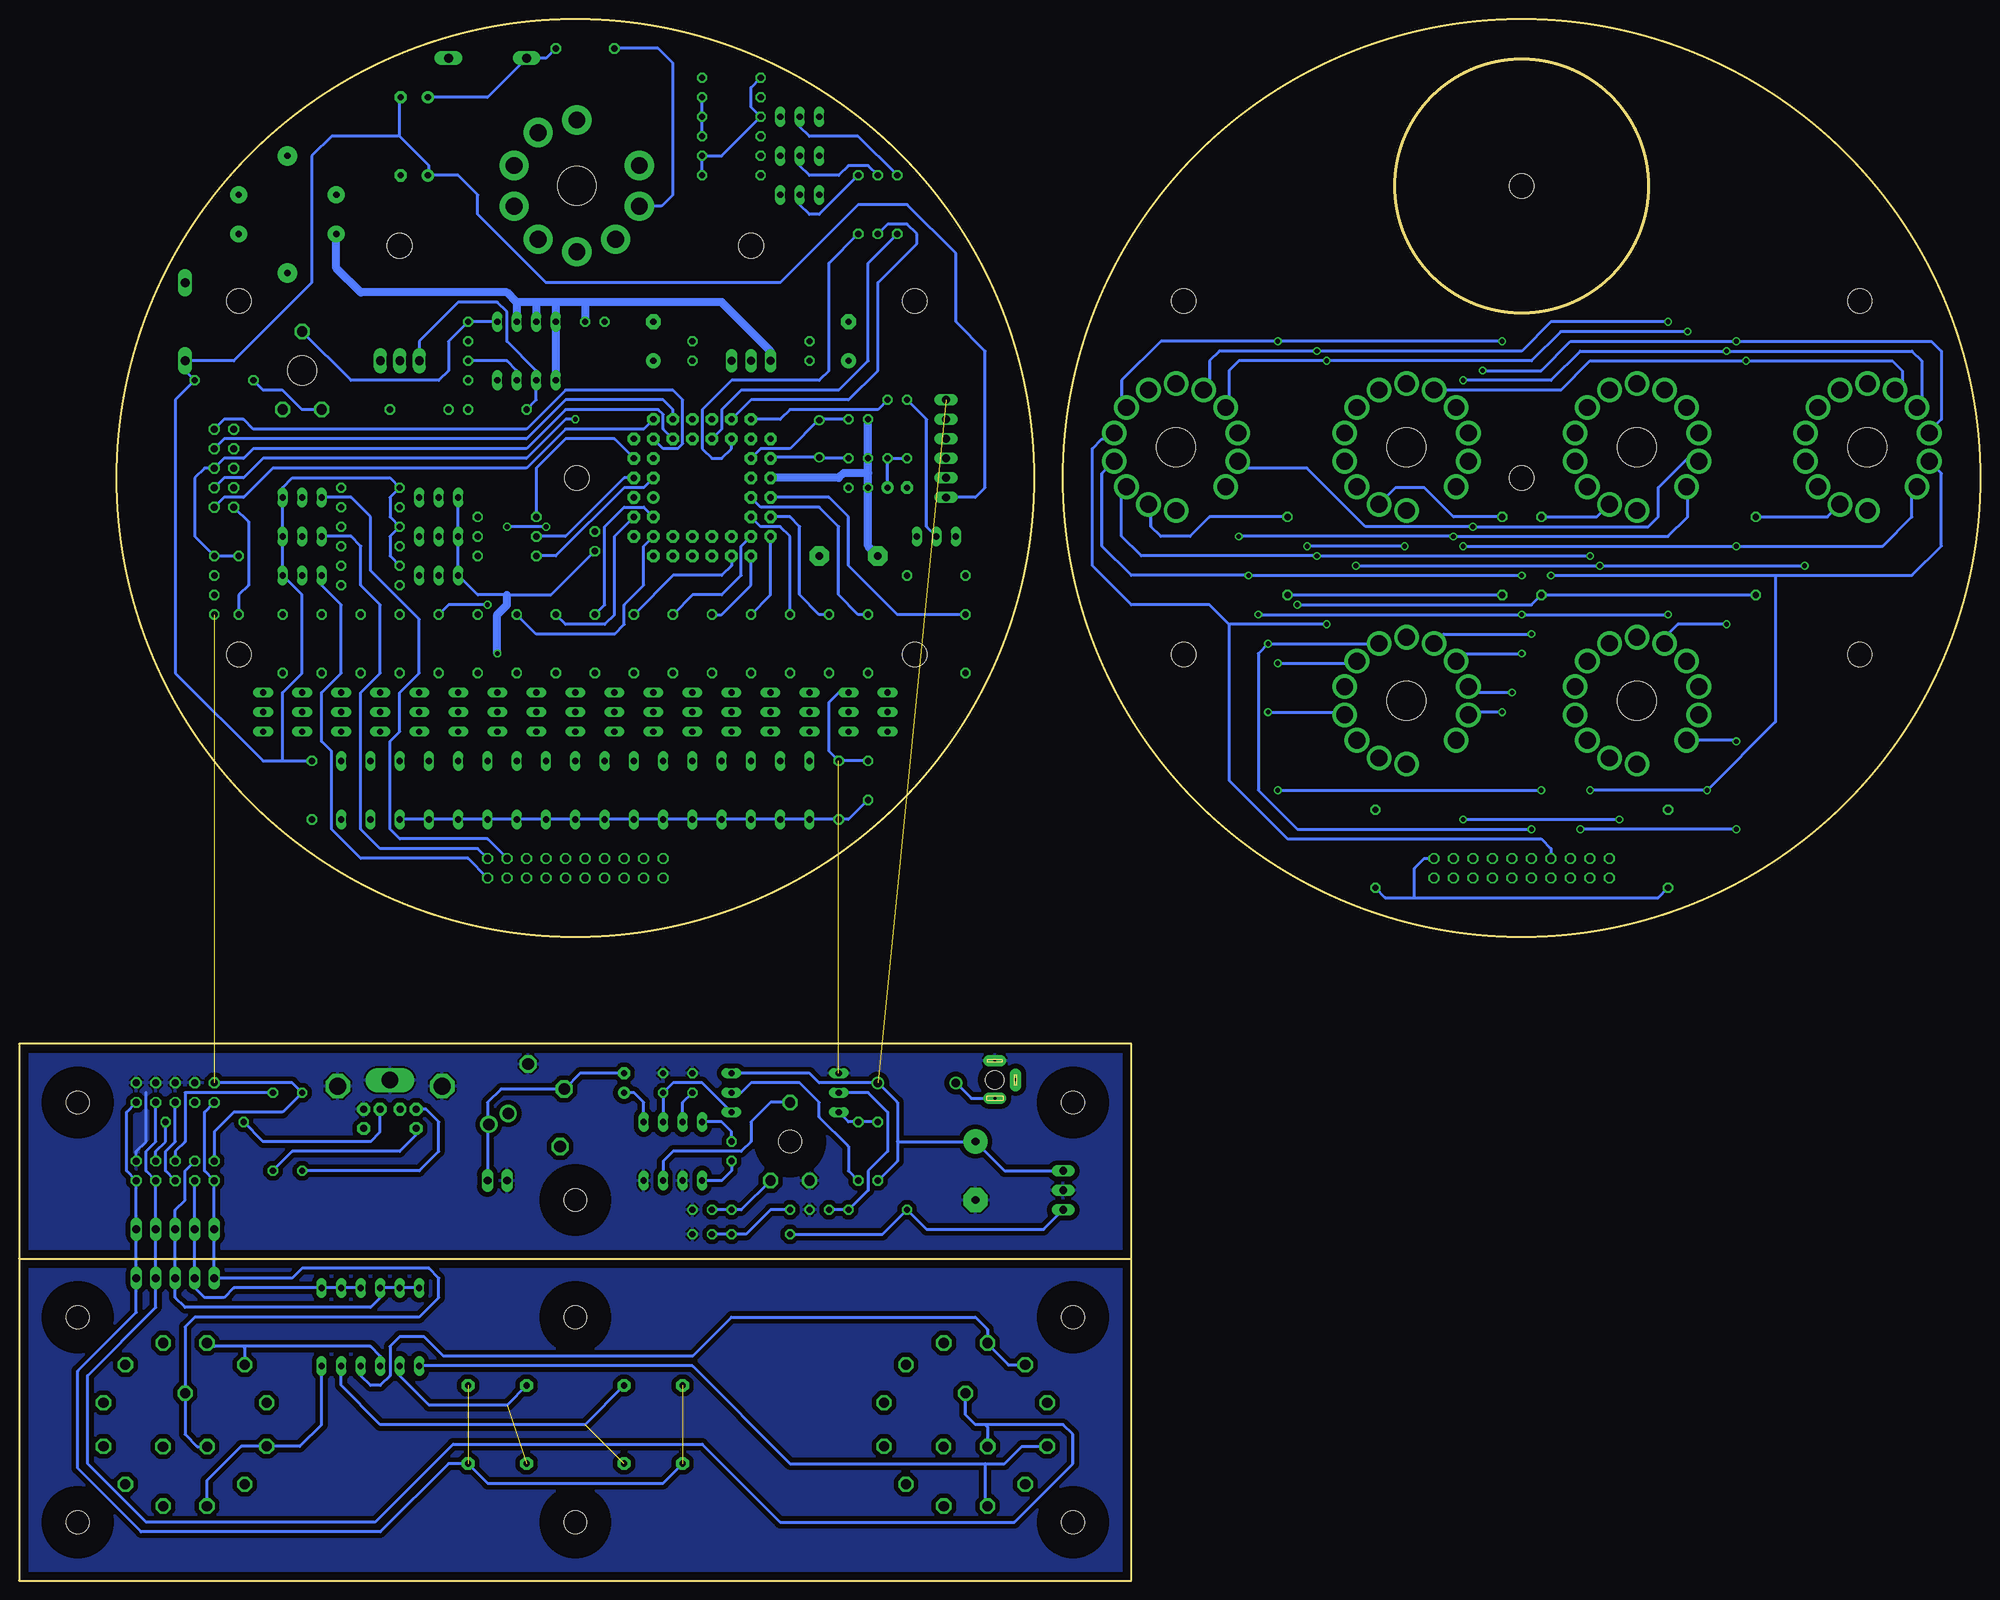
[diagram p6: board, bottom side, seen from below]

Size 255.27 x 203.2 mm. Coordinates in mm from the lower left corner, seen from the top.
Outline: 255.27,41.91 255.27,69.85 110.49,69.85 110.49,41.91
Outline: 255.27,41.91 255.27,0 110.49,0 110.49,41.91
Outline: 255.27,41.91 110.49,41.91
Outline: circle at 59.69,143.51 radius 59.69
Outline: circle at 182.88,143.51 radius 59.69
Outline: circle at 59.69,181.51 radius 16.49
Copper layers (1*16): Top 0.035mm / dielectric 1.5mm / Bottom 0.035mm
Design rules "default": minimum track width 10mil, minimum drill 24mil, track to track 8mil, track to pad 8mil, pad to pad 8mil, via to via 8mil, smd to smd 8mil, copper to edge 40mil, drill to drill 8mil, minimum pad ring 10mil, minimum via ring 8mil, stop-mask expansion 4mil, vias tented up to drill 0mil, thermal gap 10mil
Holes 5.08 mm at 14.69,147.51 44.69,147.51 74.69,147.51 104.69,147.51 74.69,114.51 44.69,114.51 182.69,181.51
Holes 3.81 mm at 218.44,157.48

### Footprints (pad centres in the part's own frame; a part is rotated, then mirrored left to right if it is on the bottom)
C025-024X044 = drill 0.813 octagon: 1 -1.27,0; 2 1.27,0
E2,5-5 = drill 0.813 pad 1.6 round: + -1.27,0 | drill 0.813 pad 1.6 octagon: - 1.27,0
E5-6 = drill 0.813 pad 1.905 round: + -2.54,0 | drill 0.813 pad 1.905 octagon: - 2.54,0
C050-024X044 = drill 0.813 octagon: 1 -2.54,0; 2 2.54,0
E3,5-10 = drill 0.813 pad 1.6 round: + -1.778,0 | drill 0.813 pad 1.6 octagon: - 1.778,0
C025-025X050 = drill 0.813 octagon: 1 -1.27,0; 2 1.27,0
E7,5-16 = drill 1.016 pad 3.15 round: + -3.81,0 | drill 1.016 pad 3.15 octagon: - 3.81,0
E2,5-6 = drill 0.813 pad 1.6 round: + -1.27,0 | drill 0.813 pad 1.6 octagon: - 1.27,0
SOD57-10 = drill 1.194 long: A 5.08,0; C -5.08,0
D-7.5 = drill 0.813 long: A 3.81,0; C -3.81,0
DO35-10 = drill 0.813 long: A 5.08,0; C -5.08,0
DO41-10 = drill 1.118 round: A 5.08,0; C -5.08,0
S44 = drill 0.813 pad 1.6 round: 1 1.27,6.35 | drill 0.813 pad 1.6 octagon: 2 -1.27,8.89; 3 -1.27,6.35; 4 -3.81,8.89; 5 -3.81,6.35; 6 -6.35,8.89; 7 -8.89,6.35; 8 -6.35,6.35; 9 -8.89,3.81; 10 -6.35,3.81; 11 -8.89,1.27; 12 -6.35,1.27; 13 -8.89,-1.27; 14 -6.35,-1.27; 15 -8.89,-3.81; 16 -6.35,-3.81; 17 -8.89,-6.35; 18 -6.35,-8.89; 19 -6.35,-6.35; 20 -3.81,-8.89; 21 -3.81,-6.35; 22 -1.27,-8.89; 23 -1.27,-6.35; 24 1.27,-8.89; 25 1.27,-6.35; 26 3.81,-8.89; 27 3.81,-6.35; 28 6.35,-8.89; 29 8.89,-6.35; 30 6.35,-6.35; 31 8.89,-3.81; 32 6.35,-3.81; 33 8.89,-1.27; 34 6.35,-1.27; 35 8.89,1.27; 36 6.35,1.27; 37 8.89,3.81; 38 6.35,3.81; 39 8.89,6.35; 40 6.35,8.89; 41 6.35,6.35; 42 3.81,8.89; 43 3.81,6.35; 44 1.27,8.89
DIL08 = drill 0.813 long: 1 -3.81,-3.81; 2 -1.27,-3.81; 3 1.27,-3.81; 4 3.81,-3.81; 5 3.81,3.81; 6 1.27,3.81; 7 -1.27,3.81; 8 -3.81,3.81
78XXL = drill 1.016 long: GND 0,-3.81; IN -2.54,-3.81; OUT 2.54,-3.81 | hole 3.302: 0,11.176
1X03 = drill 1.016 long: 1 -2.54,0; 2 0,0; 3 2.54,0
1X05 = drill 1.016 long: 1 -5.08,0; 2 -2.54,0; 3 0,0; 4 2.54,0; 5 5.08,0
1X02 = drill 1.016 long: 1 -1.27,0; 2 1.27,0
0207/10 = drill 0.813 octagon: 1 -5.08,0; 2 5.08,0
NIXIE-13 = drill 2.184 pad 3.2 round: 1 0,-8.257; 2 3.583,-7.439; 3 6.456,-5.148; 4 8.05,-1.837; 5 8.05,1.837; 6 6.456,5.148; 7 3.583,7.439; 8 0,8.257; 9 -3.583,7.439; 10 -6.456,5.148; 11 -8.05,1.837; 12 -8.05,-1.837; 13 -6.456,-5.148
HC49/S = drill 0.813 round: 1 -2.413,0; 2 2.413,0
TO220AHS = drill 1.118 long: B -2.54,-3.81; C 0,-3.81; E 2.54,-3.81 | hole 3.302: 0,11.176
0204/7 = drill 0.813 octagon: 1 -3.81,0; 2 3.81,0
LI10 = drill 1.321 octagon: A -2.54,-5.08; E 2.54,-5.08; S 0,5.08
0207/7 = drill 0.813 octagon: 1 -3.81,0; 2 3.81,0
CK103X04 = drill 1.321 octagon: A -2.87,-2.87; A1 -2.845,-10.617; A2 -7.772,-7.772; A3 -10.617,-2.845; A4 -10.617,2.845; B 0,4.059; B1 -7.772,7.772; B2 -2.845,10.617; B3 2.845,10.617; B4 7.772,7.772; C 2.87,-2.87; C1 10.617,2.845; C2 10.617,-2.845; C3 7.772,-7.772; C4 2.845,-10.617
MEC1ZC = drill 0.813 pad 1.676 octagon: 1 -3.81,5.08; 2 -3.81,-5.08; 3 3.81,5.08; 4 3.81,-5.08
F/CM12P = drill 1.016 pad 2.54 octagon: + 3.81,0; - -3.81,0
ML20 = drill 0.914 octagon: 1 -11.43,-1.27; 2 -11.43,1.27; 3 -8.89,-1.27; 4 -8.89,1.27; 5 -6.35,-1.27; 6 -6.35,1.27; 7 -3.81,-1.27; 8 -3.81,1.27; 9 -1.27,-1.27; 10 -1.27,1.27; 11 1.27,-1.27; 12 1.27,1.27; 13 3.81,-1.27; 14 3.81,1.27; 15 6.35,-1.27; 16 6.35,1.27; 17 8.89,-1.27; 18 8.89,1.27; 19 11.43,-1.27; 20 11.43,1.27
ML10 = drill 0.914 octagon: 1 -5.08,-1.27; 2 -5.08,1.27; 3 -2.54,-1.27; 4 -2.54,1.27; 5 0,-1.27; 6 0,1.27; 7 2.54,-1.27; 8 2.54,1.27; 9 5.08,-1.27; 10 5.08,1.27
ML10L = drill 0.914 octagon: 1 -5.08,-1.27; 2 -5.08,1.27; 3 -2.54,-1.27; 4 -2.54,1.27; 5 0,-1.27; 6 0,1.27; 7 2.54,-1.27; 8 2.54,1.27; 9 5.08,-1.27; 10 5.08,1.27
TO92-CBE = drill 0.813 long: B 0,0; C 2.54,0; E -2.54,0
TO92-EBC = drill 0.813 long: B 0,-1.27; C -2.54,-1.27; E 2.54,-1.27
TOROID = drill 0.813 pad 2.184 round: P1 -2.54,6.35; P2 -2.54,-6.35; S1 2.54,6.35; S2 2.54,-6.35 | drill 0.813 pad 2.54 round: P$1 -7.62,0; P$2 7.62,0
DEKATRON = drill 2.184 pad 3.81 round: P1 -8.15,2.648; P2 -8.15,-2.648; P3 -5.037,-6.933; P4 0,-8.569; P5 5.037,-6.933; P6 8.15,-2.648; P7 8.15,2.648; P8 5.037,6.933; P9 0,8.569
3,2 = hole 3.2: 0,0
3,0 = hole 3: 0,0
733989-5 = drill 0.4 pad 1.5 long: 1 0,5.82; 3 2.7,3.42 | drill 0.3 pad 1.5 long: 2 0,0.92 | hole 2.4: 0,3.42
PG203J = drill 1.499 octagon: 1 -5.004,-0.203; 4 5.74,-4.369; 5 -1.753,-4.902 | drill 1.499 round: 2 2.845,4.902; 3 1.448,2.388
MINI-6 = drill 0.9 pad 1.676 octagon: A -3.4,-8.5; B -1.3,-8.5; C 1.3,-8.5; D 3.4,-8.5; E -3.4,-11; H 3.4,-11 | drill 2.184 pad 2.54 long: M 0,-4.7 | drill 2.184 pad 2.8 octagon: M1 -6.8,-5.5; M2 6.8,-5.5

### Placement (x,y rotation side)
C1  229.87,132.08 90 top
C2  146.05,146.05 0 top
C3  146.05,151.13 0 top
C4  140.97,142.24 180 top
C5  147.32,161.29 90 top
C6  172.72,161.29 90 top
C7  152.4,160.02 90 top
C8  196.85,157.48 270 top
C9  196.85,162.56 270 top
C10  167.64,160.02 90 top
C11  180.34,163.83 180 top
C12  146.05,142.24 180 top
C13  180.34,135.25 270 top
C14  229.87,127 90 top
C15  144.78,104.14 90 top
C16  203.84,193.04 0 top
C17  203.84,182.88 0 top
C18  166.37,45.08 0 top
C19  130.81,53.34 270 top
C20  166.37,48.26 180 top
C21  162.56,55.88 270 top
C22  167.64,64.77 270 top
C23  171.45,64.77 270 top
C24  151.13,48.26 0 top
C25  176.53,64.77 90 top
D1  233.68,163.83 90 top
D3  152.4,102.87 90 top
D4  156.21,102.87 90 top
D5  160.02,102.87 90 top
D6  163.83,102.87 90 top
D7  167.64,102.87 90 top
D8  171.45,102.87 90 top
D9  175.26,102.87 90 top
D10  179.07,102.87 90 top
D11  182.88,102.87 90 top
D12  186.69,102.87 90 top
D13  190.5,102.87 90 top
D14  194.31,102.87 90 top
D15  198.12,102.87 90 top
D16  201.93,102.87 90 top
D17  205.74,102.87 90 top
D18  209.55,102.87 90 top
D19  213.36,102.87 90 top
D20  194.31,198.12 0 top
D21  208.28,33.02 90 top
D22  215.9,33.02 90 top
D23  205.74,33.02 90 top
D24  213.36,33.02 90 top
D25  203.2,33.02 90 top
D26  210.82,33.02 90 top
D27  138.43,64.77 180 top
IC1  166.37,142.24 270 top
IC2  189.23,160.02 0 top
IC3  170.18,55.88 0 top
IC4  160.02,162.56 0 top
JP1  134.62,151.13 90 top
JP2  134.62,143.51 90 top
JP3  234.95,45.72 0 top
JP4  234.95,39.37 0 top
JP5  119.38,50.8 90 top
JP6  193.04,52.07 180 top
L1  231.14,59.69 180 top
L2  218.44,58.42 270 top
L3  222.25,58.42 270 top
NIX1  74.69,114.51 0 top
NIX2  44.69,114.51 0 top
NIX3  104.69,147.51 0 top
NIX4  74.69,147.51 0 top
NIX5  44.69,147.51 0 top
NIX6  14.69,147.51 0 top
Q1  151.13,148.59 270 top
Q2  205.74,162.56 0 top
R1  220.98,121.92 270 top
R2  209.55,137.16 180 top
R3  226.69,129.54 270 top
R4  215.9,121.92 270 top
R5  210.82,121.92 270 top
R6  205.74,121.92 270 top
R7  200.66,121.92 270 top
R8  195.58,121.92 270 top
R9  190.5,121.92 270 top
R10  185.42,121.92 270 top
R11  180.34,121.92 270 top
R12  175.26,121.92 270 top
R13  170.18,121.92 270 top
R14  165.1,121.92 270 top
R15  160.02,121.92 270 top
R16  154.94,121.92 270 top
R17  149.86,121.92 270 top
R18  144.78,121.92 270 top
R19  132.08,121.92 270 top
R20  191.77,135.89 0 top
R21  191.77,133.35 0 top
R22  191.77,138.43 0 top
R23  29.21,133.35 270 top
R24  57.15,133.35 270 top
R25  62.23,133.35 270 top
R26  90.17,133.35 270 top
R27  40.64,95.25 270 top
R28  78.74,95.25 270 top
R29  209.55,132.08 180 top
R30  209.55,139.7 0 top
R31  209.55,134.62 0 top
R32  209.55,129.54 0 top
R33  209.55,142.24 180 top
R34  228.6,156.21 0 top
R35  203.2,152.4 0 top
R36  193.04,152.4 180 top
R37  218.44,157.48 0 top
R38  217.17,102.87 90 top
R39  148.59,102.87 270 top
R40  140.97,179.07 90 top
R41  143.51,179.07 90 top
R42  135.89,130.81 180 top
R43  139.7,149.86 90 top
R44  142.24,149.86 270 top
R45  146.05,179.07 90 top
R46  162.56,187.96 0 top
R47  162.56,185.42 0 top
R48  162.56,182.88 0 top
R49  162.56,195.58 0 top
R50  162.56,190.5 180 top
R51  181.61,199.39 0 top
R52  162.56,193.04 0 top
R53  158.75,45.08 0 top
R54  154.94,57.15 0 top
R55  143.51,48.26 0 top
R56  146.05,55.88 270 top
R57  143.51,55.88 270 top
R58  158.75,48.26 0 top
S1  233.68,20.32 0 top
S2  132.08,20.32 0 top
S3  193.04,20.32 0 top
S4  172.72,20.32 0 top
SG1  147.32,133.35 0 top
SV1  59.69,92.71 180 top
SV2  182.88,92.71 180 top
SV3  228.6,144.78 90 top
SV4  234.95,53.34 0 top
SV5  234.95,63.5 0 top
T1  218.44,113.03 270 top
T2  213.36,113.03 270 top
T3  208.28,113.03 270 top
T4  203.2,113.03 270 top
T5  198.12,113.03 270 top
T6  193.04,113.03 270 top
T7  187.96,113.03 270 top
T8  182.88,113.03 270 top
T9  177.8,113.03 270 top
T10  172.72,113.03 270 top
T11  167.64,113.03 270 top
T12  162.56,113.03 270 top
T13  157.48,113.03 270 top
T14  152.4,113.03 270 top
T15  147.32,113.03 270 top
T16  142.24,113.03 270 top
T17  200.66,140.97 0 top
T18  200.66,130.81 0 top
T19  200.66,135.89 0 top
T20  223.52,113.03 270 top
T21  135.89,135.89 180 top
T22  153.67,190.5 0 top
T23  153.67,185.42 0 top
T24  218.44,140.97 180 top
T25  218.44,130.81 180 top
T26  218.44,135.89 180 top
T27  153.67,180.34 0 top
T28  161.29,63.5 90 top
T29  147.32,63.5 90 top
U$1  220.34,177.8 90 top
U$2  182.69,181.51 0 top
U$3  [3,2]  59.69,143.51 0 top
U$4  [3,2]  103.69,120.51 0 top
U$5  [3,2]  15.69,120.51 0 top
U$6  [3,2]  59.69,181.51 0 top
U$7  [3,2]  15.69,166.51 0 top
U$8  [3,2]  103.69,166.51 0 top
U$9  [3,2]  182.69,143.51 0 top
U$10  [3,2]  138.69,120.51 0 top
U$11  [3,2]  138.69,166.51 0 top
U$12  [3,2]  226.69,120.51 0 top
U$13  [3,2]  226.69,166.51 0 top
U$14  [3,0]  118.11,34.29 0 top
U$15  [3,0]  118.11,7.62 0 top
U$16  [3,0]  247.65,7.62 0 top
U$17  [3,0]  247.65,34.29 0 top
U$18  [3,0]  118.11,62.23 0 top
U$19  [3,0]  247.65,62.23 0 top
U$20  [3,0]  182.88,49.53 0 top
U$21  [3,0]  182.88,34.29 0 top
U$22  [3,0]  182.88,7.62 0 top
U$23  [3,0]  154.94,57.15 0 top
X1  128.27,68.58 180 top
X2  189.23,62.23 270 top
X5  207.01,69.85 0 top

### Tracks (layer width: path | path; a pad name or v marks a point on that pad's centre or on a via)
+5V  (via drill 0.61)  (1 unrouted)
  Top 0.406: IC1.44 179.7,136.52 C13.1 186.06,136.52 v186.69,137.16 | SV3.2 222.25,144.78 194.31,144.78 191.77,142.24 v191.77,137.16 | IC1.44 173.99,142.24 154.94,142.24 | 154.94,140.97 156.21,139.7 173.99,139.7 IC1.44 | R3.2 C14.1
  Top 1.016: 154.94,142.24 154.94,152.4 157.48,154.94 160.02,154.94 162.56,157.48 IC4.OUT C10.1 C6.+ | 154.94,142.24 154.94,140.97 | C12.1 154.94,142.24
  Bottom 0.406: v186.69,137.16 v191.77,137.16 | R3.2 226.69,128.27 225.43,129.54 225.43,137.79 SV3.2 | SV5.2 219.71,64.77 L2.1 220.98,60.96 227.33,60.96 229.87,58.42 SV4.2
+9V  (1 unrouted)
  Top 1.016: IC4.IN C7.1 C5.+ 137.16,158.75 134.62,156.21 JP1.3
  Bottom 0.406: R57.2 140.97,54.61 140.97,57.15 | 140.97,57.15 140.97,62.23 D27.C 151.13,64.77 152.4,66.04 T28.E | 140.97,57.15 C19.+ 127,53.34 JP5.3
  Bottom 1.016: 181.61,166.37 163.83,166.37 157.48,160.02 IC4.IN | 181.61,166.37 185.42,166.37 | 185.42,166.37 187.96,166.37 | 187.96,166.37 190.5,166.37 | 185.42,166.37 IC2.8 IC2.1 | 187.96,166.37 IC2.7 | U$1.P1 214,170.81 210.82,167.64 191.77,167.64 190.5,166.37 | 190.5,166.37 IC2.6 | 181.61,166.37 C11.1
+180V
  Bottom 0.406: 220.98,106.68 R38.2 | R29.2 207.01,133.35 207.01,135.89 R2.2 207.01,138.43 207.01,140.97 R33.2 207.01,143.51 219.71,143.51 220.98,142.24 T24.E T26.E T25.E 218.44,128.27 218.44,118.11 220.98,115.57 220.98,106.68 | JP2.1 130.81,140.97 129.54,142.24 129.54,160.02 133.35,163.83 133.35,172.72 139.7,179.07 146.05,179.07 156.21,168.91 186.69,168.91 195.58,177.8 195.58,180.34 198.12,182.88 201.93,182.88 | 201.93,182.88 C17.+ | 205.74,187.96 214.63,187.96 217.17,185.42 217.17,168.91 227.33,158.75 D1.C 233.68,157.48 R34.2 234.95,153.67 234.95,118.11 223.52,106.68 220.98,106.68 | 205.74,187.96 201.93,184.15 201.93,182.88 | C16.- 205.74,192.91 205.74,187.96
+420V
  Top 0.406: R49.2 181.61,195.58 R51.2
  Bottom 0.406: C16.+ 194.31,193.04 D20.C 186.69,198.12 R51.2
C1
  Bottom 0.406: SV4.3 JP3.2 JP4.2 232.41,38.1 231.14,36.83 228.6,36.83 227.33,38.1 D22.A D24.A D26.A
C2
  Bottom 0.406: SV4.4 233.68,53.34 233.68,49.53 234.95,48.26 JP3.3 JP4.3 234.95,36.83 233.68,35.56 209.55,35.56 208.28,36.83 D21.A D23.A D25.A
G0_
  Bottom 0.406: R40.2 146.05,187.96 152.4,187.96 153.67,189.23 T22.B
GND  (via drill 0.61)  (1 unrouted)
  Top 0.406: T16.E 143.51,116.84 143.51,120.65 | T20.E 222.25,116.84 222.25,119.38 220.98,120.65 222.25,121.92 222.25,133.35 226.06,137.16 231.14,137.16 | T15.E 147.32,120.65 | 152.4,120.65 T14.E | 157.48,120.65 T13.E | 162.56,120.65 T12.E | 167.64,120.65 T11.E | 172.72,120.65 T10.E | 177.8,120.65 T9.E | 182.88,120.65 T8.E | 187.96,120.65 T7.E | v193.04,120.65 T6.E | 198.12,120.65 T5.E | 203.2,120.65 T4.E | 208.28,120.65 T3.E | 213.36,120.65 T2.E | 218.44,120.65 T1.E | R52.1 152.4,193.04 151.13,191.77 T22.E T23.E T27.E 151.13,167.64 C5.- | SV3.10 228.6,151.13 231.14,151.13 233.68,148.59 233.68,139.7 231.14,137.16 | 231.14,137.16 231.14,132.08 C1.1 C14.2
  Top 1.016: 220.98,120.65 218.44,120.65 213.36,120.65 208.28,120.65 203.2,120.65 198.12,120.65 v193.04,120.65 187.96,120.65 182.88,120.65 177.8,120.65 172.72,120.65 167.64,120.65 162.56,120.65 157.48,120.65 152.4,120.65 147.32,120.65 143.51,120.65 143.51,124.46 139.7,128.27 | 132.08,151.13 129.54,148.59 129.54,130.81 132.08,128.27 139.7,128.27 | 147.32,161.29 134.62,161.29 132.08,158.75 132.08,151.13 | 147.32,161.29 C7.2 160.02,161.29 | 160.02,161.29 C10.2 172.72,161.29 | 172.72,161.29 C6.- | 147.32,161.29 C5.- | 196.85,154.94 C8.2 IC2.4 193.04,161.29 | 196.85,154.94 R36.1 R35.1 | 172.72,161.29 179.07,161.29 | 179.07,161.29 193.04,161.29 | 193.04,161.29 194.94,161.29 | 194.94,161.29 C9.2 | Q2.E 208.28,156.21 207.01,154.94 196.85,154.94 | 139.7,128.27 R42.1 139.7,133.35 | 139.7,133.35 139.7,135.89 | 139.7,135.89 C4.- | 139.7,135.89 T21.E | 179.07,161.29 C11.2 | 194.94,161.29 194.94,175.89 198.75,179.7 203.84,179.7 205.61,181.48 C17.- | 160.02,161.29 IC4.GND | 139.7,133.35 SG1.- | 132.08,151.13 JP1.2
  Bottom 0.406: T15.E 148.59,115.57 149.86,114.3 149.86,107.95 R39.1 C15.2 | T17.E T19.E T18.E 195.58,128.27 191.77,128.27 186.06,128.27 C13.2 | SV4.10 240.03,55.88 238.76,57.15 238.76,63.5
  Bottom 1.016: C3.1 C2.1 144.78,144.14 | 144.78,144.14 C12.2 144.78,134.62 SG1.- | 144.78,144.14 147.95,144.14 148.59,143.51 IC1.22 | v193.04,120.65 193.04,125.73 191.77,127 191.77,128.27
  pour Top: 153.67,161.29 153.67,177.8 166.37,177.8 166.37,161.29
  pour Bottom (isolate 0.61): 111.76,68.58 254,68.58 254,43.18 111.76,43.18
N$1
  Bottom 0.406: IC1.20 157.35,146.18 Q1.2 151,146.05 C2.2
N$2
  Bottom 0.406: IC1.21 158.75,147.32 154.94,147.32 151.26,151 Q1.1 151,151.13 C3.2
N$3
  Top 0.406: R4.1 212.09,121.92 171.45,121.92 168.91,124.46 168.91,134.62 IC1.36
N$4
  Bottom 0.406: IC1.10 171.45,149.86 171.45,151.76 172.08,152.4 184.15,152.4 189.23,147.32 224.79,147.32 226.06,146.05 228.6,146.05 SV3.5 231.14,144.78 232.41,143.51 232.41,135.89 C1.2 R3.1
N$5
  Top 0.406: R5.1 208.28,123.19 175.26,123.19 170.18,128.27 IC1.37
N$6
  Top 0.406: R6.1 204.47,124.46 179.07,124.46 171.45,132.08 171.45,134.62 IC1.38
N$7  (via drill 0.61)
  Top 0.406: v194.31,127 179.07,127 IC1.39
  Bottom 0.406: R7.1 199.39,127 v194.31,127
N$8
  Top 0.406: R8.1 195.58,128.27 193.04,130.81 180.34,130.81 IC1.40
N$9
  Bottom 0.406: R9.1 187.96,123.19 177.8,123.19 176.53,124.46 176.53,127 173.99,129.54 173.99,134.62 IC1.41
N$10
  Bottom 0.406: R10.1 184.15,124.46 179.07,124.46 177.8,125.73 177.8,135.89 IC1.42
N$11
  Bottom 0.406: R11.1 179.07,127 179.07,137.16 176.53,139.7 173.99,139.7 IC1.43
N$12
  Bottom 0.406: R12.1 170.18,130.81 163.83,130.81 162.56,132.08 IC1.31
N$13
  Bottom 0.406: R13.1 167.64,128.27 163.83,128.27 161.29,130.81 161.29,134.62 IC1.30
N$14
  Bottom 0.406: R14.1 163.83,125.73 160.02,129.54 IC1.29
N$15
  Bottom 0.406: R15.1 157.48,128.27 IC1.28
N$16
  Bottom 0.406: R16.1 154.94,135.89 156.21,137.16 158.75,137.16 IC1.27
N$17
  Bottom 0.406: R17.1 151.13,125.73 153.67,128.27 153.67,137.16 154.94,138.43 IC1.26
N$18
  Bottom 0.406: R18.1 146.05,125.73 148.59,128.27 148.59,137.16 151.13,139.7 158.75,139.7 IC1.25
N$19
  Bottom 0.406: R19.1 140.97,125.73 147.32,132.08 147.32,138.43 149.86,140.97 IC1.24
N$20
  Bottom 0.406: IC1.2 176.53,143.51 184.15,135.89 R20.1
N$21
  Bottom 0.406: IC1.3 173.99,142.24 176.53,142.24 185.42,133.35 R21.1
N$22
  Bottom 0.406: IC1.4 177.8,148.59 184.15,148.59 187.96,144.78 R22.1
N$23
  Top 0.406: T24.B 218.44,139.7 217.17,138.43 214.63,138.43 R30.2 R33.1
N$24
  Top 0.406: R4.2 215.9,115.57 T1.B
N$25
  Top 0.406: R5.2 210.82,115.57 T2.B
N$26
  Bottom 0.406: NIX6.2 19.91,138.43 R23.1
N$27
  Bottom 0.406: NIX5.2 49.91,138.43 R24.1
N$28
  Bottom 0.406: R25.1 68.58,138.43 72.39,142.24 76.1,142.24 NIX4.2
N$29
  Bottom 0.406: NIX3.2 107.95,139.75 107.95,137.16 106.68,135.89 102.87,135.89 100.33,138.43 R26.1
N$30
  Top 0.406: NIX2.2 48.27,107.94 46.99,109.22 43.18,109.22 41.91,107.95 41.91,101.6 R27.1
N$31
  Top 0.406: NIX1.2 78.74,106.6 R28.1
N$32
  Top 0.406: R6.2 205.74,115.57 T3.B
N$33
  Top 0.406: R7.2 200.66,115.57 T4.B
N$34
  Top 0.406: R8.2 195.58,115.57 T5.B
N$35
  Top 0.406: R9.2 190.5,115.57 T6.B
N$36
  Top 0.406: R10.2 185.42,115.57 T7.B
N$37
  Top 0.406: R11.2 180.34,115.57 T8.B
N$38
  Top 0.406: R12.2 175.26,115.57 T9.B
N$39
  Top 0.406: R13.2 170.18,115.57 T10.B
N$40
  Top 0.406: R14.2 165.1,115.57 T11.B
N$41
  Top 0.406: R15.2 160.02,115.57 T12.B
N$42
  Top 0.406: R16.2 154.94,115.57 T13.B
N$43
  Top 0.406: R17.2 149.86,115.57 T14.B
N$44
  Top 0.406: R18.2 144.78,115.57 T15.B
N$45
  Top 0.406: T16.B 137.16,113.03 R19.2
N$46
  Top 0.406: T16.C 142.24,106.68 144.78,104.14 149.86,104.14 D3.A 154.94,104.14 154.94,95.25 158.75,91.44 SV2.20
N$47
  Top 0.406: SV2.19 161.29,93.98 158.75,96.52 158.75,104.14 D4.A 153.67,109.22 148.59,109.22 T15.C
N$48
  Top 0.406: SV2.18 172.72,92.71 172.72,95.25 163.83,95.25 161.29,97.79 161.29,105.41 D5.A 158.75,106.68 154.94,110.49 T14.C
N$49
  Top 0.406: SV2.17 173.99,95.25 172.72,96.52 167.64,96.52 165.1,99.06 165.1,105.41 D6.A 162.56,106.68 158.75,110.49 T13.C
N$50
  Top 0.406: SV2.16 175.26,92.71 175.26,95.25 172.72,97.79 172.72,101.6 D7.A 163.83,110.49 T12.C
N$51
  Top 0.406: SV2.15 176.53,95.25 173.99,97.79 173.99,104.14 D8.A 171.45,107.95 168.91,110.49 T11.C
N$52
  Top 0.406: SV2.14 177.8,92.71 177.8,95.25 176.53,96.52 176.53,105.41 D9.A 175.26,107.95 T10.C
N$53
  Top 0.406: T9.C 179.07,109.22 D10.A 177.8,105.41 177.8,96.52 179.07,95.25 SV2.13
N$54
  Top 0.406: SV2.12 180.34,92.71 180.34,104.14 D11.A T8.C
N$55
  Top 0.406: SV2.11 181.61,101.6 D12.A 186.69,109.22 T7.C
N$56
  Top 0.406: T6.C 190.5,107.95 D13.A 189.23,106.68 184.15,101.6 184.15,96.52 182.88,95.25 182.88,92.71 SV2.10
N$57
  Top 0.406: T5.C 196.85,110.49 194.31,107.95 D14.A 191.77,104.14 187.96,104.14 185.42,101.6 185.42,96.52 184.15,95.25 SV2.9
N$58
  Top 0.406: T4.C 200.66,110.49 198.12,107.95 D15.A 194.31,102.87 190.5,102.87 187.96,100.33 187.96,97.79 185.42,95.25 185.42,92.71 SV2.8
N$59
  Top 0.406: T3.C 205.74,110.49 D16.A 199.39,104.14 196.85,104.14 194.31,101.6 190.5,101.6 189.23,100.33 189.23,97.79 186.69,95.25 SV2.7
N$60
  Top 0.406: T2.C 210.82,110.49 207.01,106.68 D17.A 201.93,102.87 196.85,102.87 195.58,101.6 195.58,97.79 194.31,96.52 189.23,96.52 187.96,95.25 187.96,92.71 SV2.6
N$61
  Top 0.406: T1.C 217.17,110.49 215.9,109.22 212.09,109.22 D18.A 207.01,104.14 204.47,104.14 201.93,101.6 198.12,101.6 196.85,100.33 196.85,96.52 195.58,95.25 190.5,95.25 SV2.5
N$62
  Top 0.406: SV2.4 193.04,92.71 201.93,92.71 203.2,93.98 203.2,100.33 205.74,102.87 213.36,102.87 | 213.36,102.87 D19.A | T20.C 223.52,107.95 218.44,102.87 213.36,102.87
N$63
  Top 0.406: R1.2 220.98,115.57 T20.B
N$64
  Top 0.406: T25.B 218.44,129.54 217.17,128.27 214.63,128.27 R32.2 R29.1
N$65
  Top 0.406: T26.B 218.44,134.62 217.17,133.35 214.63,133.35 R31.2 R2.1
N$66
  Top 0.406: T19.C 204.47,134.62 R31.1
N$67
  Top 0.406: T18.C 204.47,129.54 R32.1
N$68
  Top 0.406: T17.C 204.47,139.7 R30.1
N$69
  Bottom 0.406: SV3.1 228.6,140.97 226.06,140.97 222.25,144.78 189.23,144.78 184.15,149.86 173.99,149.86 IC1.7
N$70
  Top 0.406: R1.1 219.71,127 212.09,127 210.82,128.27 198.12,128.27 189.23,137.16 189.23,144.78 185.42,148.59 IC1.6
N$71
  Top 0.406: R22.2 195.58,142.24 196.85,143.51 199.39,143.51 200.66,142.24 T17.B
N$72
  Top 0.406: R21.2 199.39,133.35 200.66,132.08 T18.B
N$73
  Top 0.406: R20.2 198.12,138.43 199.39,138.43 200.66,137.16 T19.B
N$74
  Bottom 0.406: JP5.1 121.92,45.72 137.16,45.72 R55.1 142.88,45.08 R53.1
N$75
  Bottom 0.406: SV2.2 196.85,93.98 210.82,93.98 214.63,97.79 214.63,107.95 215.9,109.22 215.9,115.57 213.36,118.11 213.36,127 215.9,129.54 T25.C
N$76
  Bottom 0.406: SV2.1 195.58,95.25 208.28,95.25 210.82,97.79 210.82,115.57 208.28,118.11 208.28,127 210.82,129.54 210.82,134.62 212.09,135.89 T26.C
N$77
  Bottom 0.406: SV3.7 228.6,148.59 189.23,148.59 184.15,153.67 171.45,153.67 170.18,152.4 IC1.9
N$78
  Bottom 0.406: SV3.9 228.6,151.13 226.06,151.13 224.79,149.86 189.23,149.86 184.15,154.94 170.18,154.94 168.91,153.67 168.91,147.95 169.55,147.32 171.45,147.32 IC1.8
N$79
  Bottom 0.406: C18.1 R53.2 160.66,45.08 157.48,48.26 R58.1
N$80
  Bottom 0.406: X1.1 131.34,62.76 D27.A
N$81
  Top 0.406: D17.C D18.C D19.C R38.1
  Bottom 0.406: D17.C D16.C D15.C D14.C D13.C D12.C D11.C D10.C D9.C D8.C D7.C D6.C D5.C D4.C D3.C R39.2 147.32,99.06 C15.1
N$82
  Bottom 0.406: C8.1 191.77,158.75 190.5,157.48 IC2.3
N$83
  Bottom 0.406: R36.2 187.96,153.67 IC2.2 187.96,157.48 191.77,161.29 191.77,165.1 193.04,166.37 198.12,166.37 203.2,161.29 Q2.B
N$84
  Top 0.406: D1.A 227.33,175.26 U$1.P2
  Top 1.016: U$1.S2 U$1.P2 220.98,175.26 217.17,171.45 210.82,171.45 205.74,166.37 Q2.C
  pour Top: 212.09,161.29 199.39,161.29 199.39,177.8 212.09,177.8
N$85
  Bottom 0.406: SV2.3 194.31,96.52 205.74,96.52 207.01,97.79 207.01,109.22 205.74,110.49 205.74,115.57 203.2,118.11 203.2,125.09 209.55,131.44 209.55,138.43 212.09,140.97 T24.C
N$86
  Bottom 0.406: IC2.5 C9.1 199.39,161.29 199.39,157.48 200.66,156.21 212.09,156.21 R37.S
N$87
  Bottom 0.406: R34.1 223.52,154.94 220.98,154.94 218.44,152.4 R37.A
N$88
  Top 0.406: R35.2 207.01,151.13 208.28,149.86 219.71,149.86 220.98,151.13 R37.E
N$89
  Bottom 0.406: S1.B2 230.33,30.94 229.87,30.48 226.06,30.48 | 226.06,30.48 209.55,30.48 208.28,29.21 D21.C | S1.B1 225.91,30.33 226.06,30.48
N$90
  Top 0.406: U$1.S1 212.09,180.34 208.28,184.15 208.28,193.04 203.2,198.12 D20.A
N$91
  Top 0.406: JP2.3 133.35,146.05 132.08,144.78 R42.2
N$92
  Top 0.406: T21.C 133.35,137.16 134.62,138.43 135.89,138.43 137.16,139.7 137.16,142.24 135.89,143.51 JP2.2
N$93
  Bottom 0.406: R48.2 R47.2 163.83,185.42 R50.2 160.02,191.77 160.02,194.31 R49.1
N$94
  Bottom 0.406: T21.B 137.16,137.16 137.16,151.13 R43.2
N$95
  Bottom 0.406: R43.1 R44.2 C4.+
N$96
  Top 0.406: U$2.P7 191.77,184.16 191.77,189.23 187.96,193.04 R52.2
  Bottom 0.406: R52.2 R50.1 R46.2
N$97
  Top 0.406: T22.C R46.1 160.02,186.69 172.72,186.69 174.54,184.87 U$2.P1
N$98
  Top 0.406: T23.C R47.1 160.02,184.15 168.91,184.15 170.18,182.88 170.18,179.07 173.99,175.26 176.97,175.26 U$2.P3
N$99
  Top 0.406: U$2.P4 182.69,172.53 180.34,170.18 176.53,170.18 166.37,180.34 161.29,180.34 R48.1 T27.C
N$100
  Bottom 0.406: U$2.P2 171.66,178.86 170.18,180.34 170.18,197.48 172.08,199.39 R51.1
N$101
  Bottom 0.406: R41.2 144.78,184.15 147.32,184.15 148.59,182.88 152.4,182.88 153.67,184.15 T23.B
N$102
  Bottom 0.406: R45.2 151.13,177.8 152.4,177.8 153.67,179.07 T27.B
N$103
  Top 0.406: SV3.4 228.6,140.97 231.14,140.97 232.41,142.24 232.41,147.32 231.14,148.59 190.5,148.59 184.15,154.94 162.56,154.94 161.29,153.67 161.29,149.86 IC1.19
N$104  (via drill 0.61)
  Top 0.406: IC1.18 158.75,147.32 173.36,147.32 173.99,147.95 173.99,149.86 175.26,151.13 v182.88,151.13
  Bottom 0.406: SV3.3 228.6,143.51 226.06,143.51 223.52,146.05 189.23,146.05 184.15,151.13 v182.88,151.13
N$105
  Top 0.406: SV3.6 224.79,147.32 190.5,147.32 184.15,153.67 166.37,153.67 165.1,152.4 IC1.13
N$106
  Top 0.406: SV3.8 228.6,146.05 228.6,144.14 227.97,143.51 226.06,143.51 223.52,146.05 190.5,146.05 184.15,152.4 168.91,152.4 IC1.11
N$107
  Bottom 0.406: D22.C 215.9,20.32 218.75,17.47 S1.A3 226.37,17.47 230.84,13 S1.A1
N$108
  Bottom 0.406: C20.2 R58.2 161.29,48.26 R54.E
N$109
  Bottom 0.406: IC3.1 163.83,52.07 162.56,53.34 C21.2
N$110
  Bottom 0.406: D25.C 167.64,27.94 154.94,15.24 129.54,15.24 | 129.08,9.7 128.91,9.52 | 129.08,9.7 S2.A1 | 129.54,15.24 129.54,10.16 129.08,9.7 | S2.A3 124.77,17.47 127,15.24 129.54,15.24
N$111
  Bottom 0.406: IC3.8 163.83,59.69 162.56,58.42 C21.1
N$112
  Bottom 0.406: IC3.3 171.45,54.61 170.18,55.88 161.29,55.88 160.02,57.15 160.02,59.69 157.48,62.23 R54.S
N$113
  Bottom 0.406: IC3.5 173.99,62.23 175.26,63.5 C25.+
N$114
  Bottom 0.406: 129.36,30.94 129.54,31.11 | 129.36,30.94 S2.B2 129.24,32.71 130.81,34.29 162.56,34.29 167.64,29.21 200.03,29.21 202.56,31.75 205.74,31.75 207.01,30.48 207.01,26.67 208.28,25.4 209.55,25.4 210.82,26.67 D26.C | S2.B1 126.52,28.09 129.36,30.94
N$115  (1 unrouted)
  Bottom 0.406: D24.C 213.36,25.4 208.28,20.32 181.61,20.32 S4.3
N$116  (1 unrouted)
  Bottom 0.406: D23.C 205.74,26.67 201.93,22.86 191.77,22.86 S3.1
N$117
  Bottom 0.406: C25.- 182.25,66.04 184.3,63.98 X2.5 192.56,63.98 194.31,62.23 194.31,59.69 194.13,59.51 X2.2 194.13,59.23 194.31,59.05 JP6.1
N$118
  Bottom 0.406: C22.2 168.91,62.23 IC3.7
N$119
  Bottom 0.406: SV5.5 234.95,57.15 236.22,55.88 236.22,53.34 SV4.5
N$120
  Bottom 0.406: IC3.6 C23.2 170.18,64.77 166.37,64.77 T28.C
N$121
  Bottom 0.406: C24.1 R55.2 144.78,50.8 144.78,53.34 142.24,55.88 142.24,60.96 144.78,63.5 T29.B
N$122
  Bottom 0.406: SV4.6 234.95,55.88 233.68,57.15 233.68,63.5 L3.1
N$123
  Bottom 0.406: SV4.8 237.49,55.88 236.22,57.15 L1.1
N$124
  Bottom 0.406: R56.2 147.32,53.34 147.32,56.51 151.13,60.32 151.13,62.23 153.67,64.77 160.02,64.77 161.29,63.5 T28.B
N$125
  Bottom 0.406: R57.1 R56.1 147.32,59.69 T29.C
N$126
  Bottom 0.406: X5.C 208.31,58.39 209.55,57.15 223.52,57.15 L1.2
N$127
  Bottom 0.406: X5.E 203.61,58.01 205.74,55.88 219.71,55.88 L3.2
N$128
  Bottom 0.406: L2.2 203.2,53.34 200.66,55.88 200.66,59.69 202.32,61.35 X5.A
N$129  (via drill 0.61)
  other vias: 118.11,34.29
N$130  (via drill 0.61)
  other vias: 118.11,7.62
N$131  (via drill 0.61)
  other vias: 182.88,34.29
N$132  (via drill 0.61)
  other vias: 182.88,7.62
N$133  (via drill 0.61)
  other vias: 247.65,7.62
N$134  (via drill 0.61)
  other vias: 247.65,34.29
N$135  (via drill 0.61)
  other vias: 247.65,62.23
N$136  (via drill 0.61)
  other vias: 182.88,49.53
N$137  (via drill 0.61)
  other vias: 118.11,62.23
N$138  (via drill 0.61)
  other vias: 154.94,57.15
N$139
  pour Bottom (isolate 0.61): 111.76,40.64 254,40.64 254,1.27 111.76,1.27
NIXIE0  (via drill 0.61)
  Top 0.406: v50.8,133.35 50.8,138.43 52.07,139.7 52.07,141.44 NIX5.3 | v86.36,133.35 86.36,111.76 83.96,109.36 NIX1.3 81,109.22 73.66,109.22 66.04,101.6 SV1.5
  Bottom 0.406: v50.8,133.35 v86.36,133.35 109.22,133.35 111.76,135.89 111.76,141.75 NIX3.3
NIXIE1  (via drill 0.61)
  Top 0.406: SV1.6 64.77,92.71 64.77,109.36 | 64.77,109.36 64.63,109.36 63.5,110.49 63.5,123.19 68.58,128.27 v68.58,135.89 | 64.77,109.36 NIX1.13 | NIX3.13 96.52,140.65 v96.52,135.89
  Bottom 0.406: v96.52,135.89 v68.58,135.89 40.64,135.89 38.1,138.43 38.1,142.23 NIX5.13
NIXIE2  (via drill 0.61)
  Top 0.406: SV1.7 63.5,107.95 62.23,109.22 v62.23,113.03 62.23,124.46 66.04,128.27 v66.04,137.16
  Bottom 0.406: NIX1.12 66.28,113.03 v62.23,113.03 | NIX3.12 95.75,144.78 87.63,144.78 80.01,137.16 v66.04,137.16 43.18,137.16 41.91,138.43 41.91,142.24 38.1,146.05 37.02,146.05 NIX5.12
NIXIE3  (via drill 0.61)
  Top 0.406: SV1.8 62.23,92.71 62.23,106.68 60.96,107.95 v60.96,115.57 60.96,124.46 v59.69,125.73 | v40.64,125.73 40.64,146.05 37.34,149.35 NIX5.11 | NIX3.11 94.74,149.35 93.98,148.59 v93.98,125.73
  Bottom 0.406: NIX1.11 65.86,115.57 v60.96,115.57 | v40.64,125.73 v59.69,125.73 v93.98,125.73
NIXIE4  (via drill 0.61)
  Top 0.406: v59.69,120.65 59.69,106.68 60.96,105.41 SV1.9 | NIX5.10 38.1,152.79 v38.1,162.56 | v85.09,158.75 85.09,142.24 82.55,139.7 82.55,130.81 80.01,128.27 73.66,128.27 68.58,123.19 68.58,120.65 68.23,120.3 NIX1.10
  Bottom 0.406: v38.1,162.56 54.61,162.56 58.42,158.75 v85.09,158.75 96.52,158.75 97.79,157.48 97.79,153.1 NIX3.10 | NIX1.10 67.24,120.65 v59.69,120.65
NIXIE5  (via drill 0.61)
  Top 0.406: NIX5.9 40.64,155.42 v40.64,163.83 | SV1.10 59.69,92.71 59.69,104.14 58.42,105.41 v58.42,123.19 | v86.36,160.02 86.36,140.97 83.82,138.43 83.82,129.54 80.01,125.73 73.66,125.73 71.11,123.18 NIX1.9
  Bottom 0.406: v40.64,163.83 55.88,163.83 59.69,160.02 v86.36,160.02 99.06,160.02 100.33,158.75 100.33,155.73 NIX3.9 | NIX1.9 71.08,121.92 71.08,121.96 69.85,123.19 v58.42,123.19
NIXIE6  (via drill 0.61)
  Top 0.406: 92.71,162.56 101.6,162.56 107.95,156.21 107.95,155.27 NIX3.7 | 92.71,162.56 v92.71,121.92 | v58.42,97.79 SV1.11 | 92.71,162.56 49.53,162.56 48.26,161.29 48.26,154.96 NIX5.7
  Bottom 0.406: NIX1.7 78.3,121.92 v92.71,121.92 93.98,120.65 93.98,102.87 88.9,97.79 v58.42,97.79
NIXIE7  (via drill 0.61)
  Top 0.406: SV1.12 57.15,92.71 v57.15,102.87 | v62.23,161.29 54.61,153.67 52.16,153.67 NIX5.6 | v91.44,102.87 v91.44,119.38 v91.44,161.29
  Bottom 0.406: v62.23,161.29 v91.44,161.29 106.68,161.29 111.76,156.21 111.76,153.27 NIX3.6 | v91.44,102.87 v57.15,102.87 | NIX1.6 81.42,119.38 v91.44,119.38
NIXIE8  (via drill 0.61)
  Top 0.406: NIX1.5 85.09,118.7 v85.09,124.46 85.09,137.16 88.9,140.97 88.9,160.02 87.63,161.29 66.04,161.29 54.1,149.35 NIX5.5
  Bottom 0.406: v85.09,124.46 97.79,124.46 | 97.79,124.46 100.33,127 110.49,127 115.57,132.08 115.57,147.32 114.3,148.59 113.5,148.59 NIX3.5 | SV1.13 55.88,95.25 57.15,96.52 90.17,96.52 97.79,104.14 97.79,124.46
NIXIE9  (via drill 0.61, 0.61 pad 1.02)
  Top 0.406: SV1.14 54.61,92.71 54.61,107.95 57.15,110.49 57.15,125.73 | v59.69,130.81 59.69,128.27 57.15,125.73 | v92.71,113.03 95.25,115.57 v95.25,130.81 | 57.15,125.73 55.88,125.73 52.07,129.54 52.07,137.16 54.61,139.7 54.61,143.8 NIX5.4
  Bottom 0.406: v59.69,130.81 v95.25,130.81 110.49,130.81 114.3,134.62 114.3,144.11 NIX3.4 | NIX1.4 83.1,113.03 v92.71,113.03
NIXIE10  (via drill 0.61)
  Top 0.406: 53.34,109.36 NIX2.3 | 53.34,109.36 SV1.15 | 53.34,109.36 55.88,111.9 55.88,123.19 49.53,129.54 v49.53,132.08 | NIX4.3 81.28,142.23 v81.28,132.08 | NIX6.3 22.86,140.65 v22.86,132.08
  Bottom 0.406: v81.28,132.08 v49.53,132.08 v22.86,132.08
NIXIE11  (via drill 0.61)
  Top 0.406: v52.07,97.79 52.07,92.71 SV1.16 | v31.75,134.62 v31.75,109.22 v31.75,97.79 | NIX4.13 67.31,141.44 v67.31,134.62
  Bottom 0.406: v67.31,134.62 v31.75,134.62 12.7,134.62 8.89,138.43 8.89,141.71 NIX6.13 | v31.75,97.79 v52.07,97.79 | NIX2.13 31.89,109.36 v31.75,109.22
NIXIE12  (via drill 0.61)
  Top 0.406: v55.88,130.81 58.42,133.35 62.23,133.35 64.77,135.89 64.77,143.8 NIX4.12 | v50.8,102.87 SV1.17 | NIX2.12 35.56,111.59 v35.56,102.87
  Bottom 0.406: v55.88,130.81 26.67,130.81 | v50.8,102.87 v35.56,102.87 26.67,111.76 26.67,130.81 | NIX6.12 5.08,144.11 5.08,134.62 8.89,130.81 26.67,130.81
NIXIE13  (via drill 0.61, 0.61 pad 1.02)
  Top 0.406: SV1.18 49.53,92.71 43.18,92.71 34.29,101.6 34.29,114.3 36.49,116.5 | 36.49,116.5 NIX2.11 | 36.49,116.5 35.9,116.5 34.29,118.11 34.29,138.43 31.75,140.97 v31.75,161.29 | NIX4.11 64.77,151.22 v64.77,157.48
  Bottom 0.406: v64.77,157.48 57.15,157.48 53.34,161.29 v31.75,161.29 6.35,161.29 5.08,160.02 5.08,151.13 6.64,149.57 NIX6.11
NIXIE14  (via drill 0.61)
  Top 0.406: SV1.19 44.45,93.98 39.37,99.06 39.37,105.41 40.64,106.68 40.64,117.25 NIX2.10 38.1,119.79 37.69,119.79 35.56,121.92 35.56,139.7 33.02,142.24 v33.02,160.02 | NIX4.10 67.31,153.58 v67.31,156.21
  Bottom 0.406: v67.31,156.21 55.88,156.21 52.07,160.02 v33.02,160.02 8.89,160.02 7.62,158.75 7.62,153.27 NIX6.10
NIXIE15  (via drill 0.61 pad 1.02)
  Top 0.406: SV1.20 41.91,91.44 33.02,100.33 v33.02,124.46 33.02,137.16 30.48,139.7 v30.48,158.75
  Bottom 0.406: NIX2.9 41.11,122.72 39.37,124.46 v33.02,124.46 | NIX6.9 10.16,155.9 10.16,157.48 11.43,158.75 v30.48,158.75 50.8,158.75 54.61,154.94 71.1,154.94 NIX4.9
NIXIEA0
  Bottom 0.406: 73.66,88.9 73.66,92.71 72.39,93.98 SV1.1 | R28.2 77.47,88.9 73.66,88.9 | 73.66,88.9 41.91,88.9 R27.2
NIXIEA1
  Top 0.406: SV1.2 72.39,91.44 76.2,95.25 82.55,95.25 90.17,102.87 R26.2
  Bottom 0.406: R26.2 R25.2
NIXIEA2  (via drill 0.61 pad 1.02)
  Top 0.406: SV1.3 68.58,95.25 71.12,97.79 82.55,97.79 88.9,104.14 v88.9,127
  Bottom 0.406: R23.2 R24.2 58.42,127 v88.9,127
NIXIEDP  (via drill 0.61, 0.61 pad 1.02)
  Top 0.406: SV1.4 67.31,92.71 v67.31,99.06 80.01,99.06 87.63,106.68 v87.63,134.62 | NIX2.1 44.69,101.36 v46.99,99.06 | NIX4.1 74.93,139.01 v74.93,134.62
  Bottom 0.406: v74.93,134.62 v87.63,134.62 | v67.31,99.06 v46.99,99.06
PD2
  Bottom 0.406: R40.1 144.78,171.45 144.78,158.75 148.59,154.94 161.29,154.94 163.83,152.4 163.83,149.86 IC1.14
PD3
  Bottom 0.406: R41.1 142.24,176.53 139.7,176.53 138.43,175.26 138.43,173.99 143.51,168.91 143.51,157.48 147.32,153.67 160.02,153.67 IC1.15
PD4
  Bottom 0.406: R45.1 149.86,171.45 149.86,157.48 151.13,156.21 162.56,156.21 166.37,152.4 166.37,147.32 165.1,146.05 163.83,146.05 162.56,147.32 IC1.16
PD5
  Bottom 0.406: IC1.17 156.21,151.13 154.94,152.4 143.51,152.4 R44.1
R1
  Bottom 0.406: S1.A 232.08,17.45 233.68,19.05 S1.B 233.68,33.02 232.41,34.29 203.2,34.29 200.66,36.83 200.66,39.37 201.93,40.64 218.44,40.64 219.71,39.37 JP4.1 JP3.1 SV4.1 231.14,53.34 231.14,60.96 SV5.1
R2
  Bottom 0.406: SV5.7 237.49,57.15 238.76,55.88 238.76,53.34 SV4.7 JP3.4 JP4.4 237.49,35.56 246.38,26.67 246.38,15.24 238.76,7.62 208.91,7.62 198.75,17.78 166.37,17.78 156.21,7.62 125.73,7.62 118.11,15.24 118.11,19.05 119.38,20.32 129.54,20.32 | S2.A 129.21,19.99 129.54,20.32 | S2.B 132.08,21.59 130.81,20.32 129.54,20.32
R3  (2 unrouted)
  Bottom 0.406: SV5.9 241.3,60.96 241.3,53.34 SV4.9 JP3.5 JP4.5 240.03,34.92 247.65,27.3 247.65,14.6 239.4,6.35 208.28,6.35 199.39,15.24 S3.4 194.31,12.7 171.45,12.7 S4.2
SPKR
  Top 0.406: IC1.32 161.29,134.62 152.4,134.62 SG1.+ 149.86,134.62 146.05,134.62 143.51,137.16 143.51,147.32 142.24,148.59 JP1.1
